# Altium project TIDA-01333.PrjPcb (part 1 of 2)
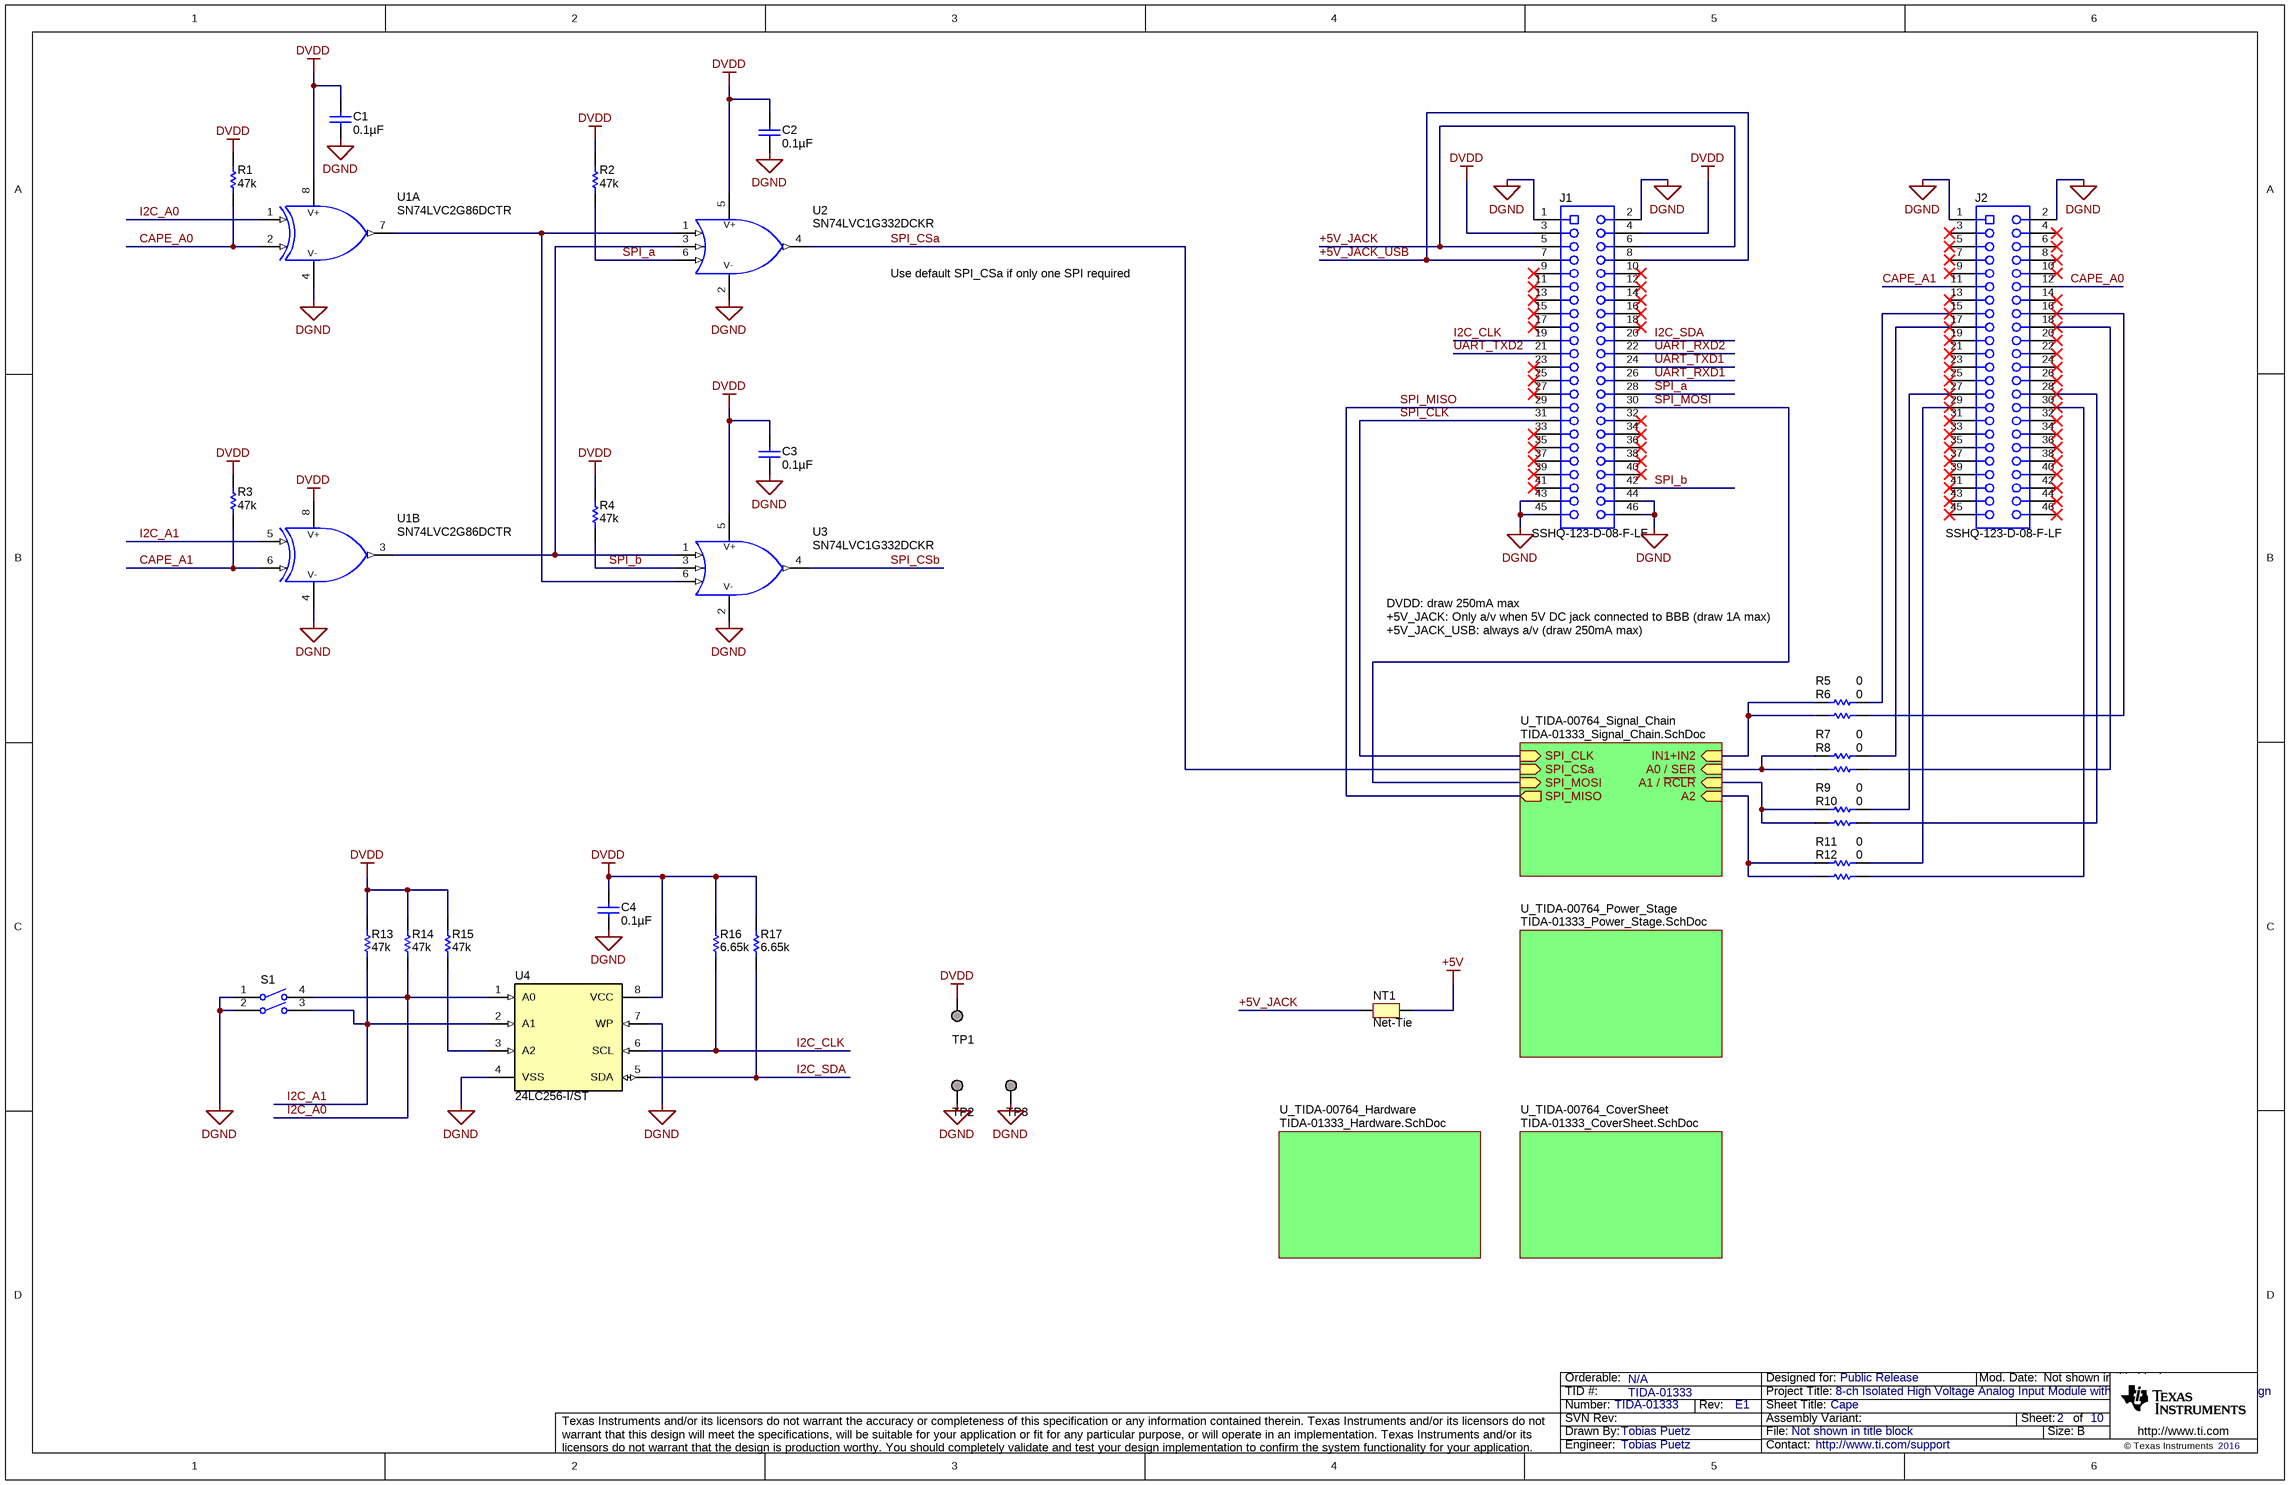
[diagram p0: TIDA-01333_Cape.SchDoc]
CopyrightYear: 2016; EVM_Orderable: N/A; PCB_Layout: Tobias Puetz; PCB_Rev: E1; PRJ_Customer: Public Release; PRJ_Engineer: Tobias Puetz; PRJ_Number: TIDA-01333; PRJ_Title: 8-ch Isolated High Voltage Analog Input Module with ISOW7841 Reference Design; SCH_Rev: E1; TechSupport: http://www.ti.com/support; TID: TIDA-01333
10 sheets, 243 parts. Net scope: hierarchical (ports join the sheet entries above them; power ports are global).
Board file: TIDA-01333.PcbDoc
Sheets:
  TIDA-01333_Cape.SchDoc
    U_TIDA-00764_Hardware = TIDA-01333_Hardware.SchDoc
    U_TIDA-00764_Signal_Chain = TIDA-01333_Signal_Chain.SchDoc
      Channel_Inputs = TIDA-01333_Channel_Inputs.SchDoc
        CMCh1 = TIDA-01333_CMCh_Input.SchDoc
        CMCh3 = TIDA-01333_CMCh_Input.SchDoc
        CMCh2 = TIDA-01333_CMCh_Input.SchDoc
        CMCh4 = TIDA-01333_CMCh_Input.SchDoc
        NoCMCh1 = TIDA-01333_Ch_Input.SchDoc
        NoCMCh2 = TIDA-01333_Ch_Input.SchDoc
        NoCMCh3 = TIDA-01333_Ch_Input.SchDoc
        NoCMCh4 = TIDA-01333_Ch_Input.SchDoc
      MUX_Stage = TIDA-01333_MUX_Stage.SchDoc
      Digital_Isolation = TIDA-01333_Digital_Isolation.SchDoc
    U_TIDA-00764_Power_Stage = TIDA-01333_Power_Stage.SchDoc
    U_TIDA-00764_CoverSheet = TIDA-01333_CoverSheet.SchDoc

## Sheet TIDA-01333_Cape.SchDoc: Cape
size 431 x 279 mm; Date: Not shown in title block; ApprovedBy: Not shown in title block; CheckedBy: Not shown in title block; Author: Not shown in title block; CompanyName: Not shown in title block; DrawnBy: Tobias Puetz; Engineer: Not shown in title block; Organization: Not shown in title block; Address1: Not shown in title block; Address2: Not shown in title block; Address3: Not shown in title block; Address4: Not shown in title block; DocumentNumber: 2; Revision: Use project parameter SCH_Rev; SheetNumber: 2; SheetTotal: 10; PageSetup: Record=PageOptions¦CenterHorizontal=True¦CenterVertical=True¦PrintScale=0.62¦XCorrection=1.00¦YCorrection=1.00¦PrintKind=0¦BorderSize=5000000¦LeftOffset=0¦BottomOffset=0¦Orientation=2¦PaperLength=1000¦PaperWidth=1000¦Scale=100¦PaperSource=15¦PrintQuality=600¦MediaType=1¦DitherType=10¦PrintScaleMode=1¦PaperKind=Letter

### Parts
C1  ValueDisplayed: 0.1µF  [0402]  (hidden comment: C1005X7R1H104K050BB)
C2  ValueDisplayed: 0.1µF  [0402]  (hidden comment: C1005X7R1H104K050BB)
C3  ValueDisplayed: 0.1µF  [0402]  (hidden comment: C1005X7R1H104K050BB)
C4  ValueDisplayed: 0.1µF  [0402]  (hidden comment: C1005X7R1H104K050BB)
J1  SSHQ-123-D-08-F-LF  [Major_BBB_SSHQ-123-D-08]
J2  SSHQ-123-D-08-F-LF  [Major_BBB_SSHQ-123-D-08]
NT1  Net-Tie  [Net-Tie_20milWide_60milLong]  (net tie, no BOM)
R1  ValueDisplayed: 47k  [0402]  (hidden comment: CRCW040247K0JNED)
R2  ValueDisplayed: 47k  [0402]  (hidden comment: CRCW040247K0JNED)
R3  ValueDisplayed: 47k  [0402]  (hidden comment: CRCW040247K0JNED)
R4  ValueDisplayed: 47k  [0402]  (hidden comment: CRCW040247K0JNED)
R5  ValueDisplayed: 0  [0603]  (hidden comment: CRCW06030000Z0EA)
R6  ValueDisplayed: 0  [0603]  (hidden comment: CRCW06030000Z0EA)
R7  ValueDisplayed: 0  [0603]  (hidden comment: CRCW06030000Z0EA)
R8  ValueDisplayed: 0  [0603]  (hidden comment: CRCW06030000Z0EA)
R9  ValueDisplayed: 0  [0603]  (hidden comment: CRCW06030000Z0EA)
R10  ValueDisplayed: 0  [0603]  (hidden comment: CRCW06030000Z0EA)
R11  ValueDisplayed: 0  [0603]  (hidden comment: CRCW06030000Z0EA)
R12  ValueDisplayed: 0  [0603]  (hidden comment: CRCW06030000Z0EA)
R13  ValueDisplayed: 47k  [0402]  (hidden comment: CRCW040247K0JNED)
R14  ValueDisplayed: 47k  [0402]  (hidden comment: CRCW040247K0JNED)
R15  ValueDisplayed: 47k  [0402]  (hidden comment: CRCW040247K0JNED)
R16  ValueDisplayed: 6.65k  [0402]  (hidden comment: CRCW04026K65FKED)
R17  ValueDisplayed: 6.65k  [0402]  (hidden comment: CRCW04026K65FKED)
S1  416131160802  [SW_416131160802]  (value not drawn)
TP1  TESTPOINT  [TESTPOINT]  (value not drawn)  (no BOM)
TP2  TESTPOINT  [TESTPOINT]  (value not drawn)  (no BOM)
TP3  TESTPOINT  [TESTPOINT]  (value not drawn)  (no BOM)
U1  SN74LVC2G86DCTR  [DCT0008A_N]  (parts A,B of 2)
U2  SN74LVC1G332DCKR  [DCK0006A_N]
U3  SN74LVC1G332DCKR  [DCK0006A_N]
U4  24LC256-I/ST  [TSSOP-8]

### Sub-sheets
U_TIDA-00764_CoverSheet = TIDA-01333_CoverSheet.SchDoc: no entries
U_TIDA-00764_Hardware = TIDA-01333_Hardware.SchDoc: no entries
U_TIDA-00764_Power_Stage = TIDA-01333_Power_Stage.SchDoc: no entries
U_TIDA-00764_Signal_Chain = TIDA-01333_Signal_Chain.SchDoc: SPI_CSa (in), SPI_CLK (in), SPI_MISO (out), SPI_MOSI (in), A2 (in), A1 / ~{RCLR} (in), A0 / SER (in), IN1+IN2 (in)

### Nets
+5V: NT1.2
DGND: C1.2 C2.2 C3.2 C4.2 J1.1 J1.2 J1.43 J1.44 J1.45 J1.46 J2.1 J2.2 S1.1 S1.2 TP2.1 TP3.1 U1.4(GND) U2.2(GND) U3.2(GND) U4.4(VSS) U4.7(WP)
DVDD: C1.1 C2.1 C3.1 C4.1 J1.3 J1.4 R1.1 R2.1 R3.1 R4.1 R13.1 R14.1 R15.1 R16.1 R17.1 TP1.1 U1.8(VCC) U2.5(VCC) U3.5(VCC) U4.8(VCC)
+5V_JACK: J1.5 J1.6 NT1.1
+5V_JACK_USB: J1.7 J1.8
A0 / SER: R7.2 R8.2 ; sheet U_TIDA-00764_Signal_Chain/A0 / SER
A1 / ~{RCLR}: R9.2 R10.2 ; sheet U_TIDA-00764_Signal_Chain/A1 / ~{RCLR}
A2: R11.2 R12.2 ; sheet U_TIDA-00764_Signal_Chain/A2
CAPE_A0: J2.12 R1.2 U1.2(1B)
CAPE_A1: J2.11 R3.2 U1.6(2B)
I2C_A0: R14.2 S1.4 U1.1(1A) U4.1(A0)
I2C_A1: R13.2 S1.3 U1.5(2A) U4.2(A1)
I2C_CLK: J1.19 R16.2 U4.6(SCL)
I2C_SDA: J1.20 R17.2 U4.5(SDA)
IN1+IN2: R5.2 R6.2 ; sheet U_TIDA-00764_Signal_Chain/IN1+IN2
SPI_a: J1.28 R2.2 U2.6(C)
SPI_b: J1.42 R4.2 U3.3(B)
SPI_CLK: J1.31 ; sheet U_TIDA-00764_Signal_Chain/SPI_CLK
SPI_CSa: U2.4(Y) ; sheet U_TIDA-00764_Signal_Chain/SPI_CSa
SPI_CSb: U3.4(Y)
SPI_MISO: J1.29 ; sheet U_TIDA-00764_Signal_Chain/SPI_MISO
SPI_MOSI: J1.30 ; sheet U_TIDA-00764_Signal_Chain/SPI_MOSI
UART_RXD1: J1.26
UART_RXD2: J1.22
UART_TXD1: J1.24
UART_TXD2: J1.21
NetJ2_15: J2.15 R5.1
NetJ2_16: J2.16 R6.1
NetJ2_17: J2.17 R7.1
NetJ2_18: J2.18 R8.1
NetJ2_27: J2.27 R9.1
NetJ2_28: J2.28 R10.1
NetJ2_29: J2.29 R11.1
NetJ2_30: J2.30 R12.1
NetR15_2: R15.2 U4.3(A2)
NetU1_3: U1.3(2Y) U2.3(B) U3.1(A)
NetU1_7: U1.7(1Y) U2.1(A) U3.6(C)

Not connected (* = marked no-connect by the designer): J1 9* 10* 11* 12* 13* 14* 15* 16* 17* 18* 23* 25* 27* 32* 33* 34* 35* 36* 37* 38* 39* 40* 41*; J2 3* 4* 5* 6* 7* 8* 9* 10* 13* 14* 19* 20* 21* 22* 23* 24* 25* 26* 31* 32* 33* 34* 35* 36* 37* 38* 39* 40* 41* 42* 43* 44* 45* 46*

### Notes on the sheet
- Use default SPI_CSa if only one SPI required
- DVDD: draw 250mA max
  +5V_JACK: Only a/v when 5V DC jack connected to BBB (draw 1A max)
  +5V_JACK_USB: always a/v (draw 250mA max)

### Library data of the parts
C1-C4 = C1005X7R1H104K050BB: CAP, CERM, 0.1 µF, 50 V, +/- 10%, X7R, 0402; Manufacturer: TDK; Polarized: N; CompType: Capacitor; Value: 0.1uF; U/M: EA; Cap_F: 0.0000001; Tolerance_%: 10; ESR_ohm: 0.039064; Value1: 0.039064 ohm; VDC_V: 50; Value2: 50V; IRMS_A: 0.814669; TaMin_C: -55; TaMax_C: 125; AEC Category: Q200; SizeArea_mm2: 0.5; SizeAreaWB_mm2: 3; SizeX_mm: 1; SizeZ_mm: 0.6
J1 J2 = SSHQ-123-D-08-F-LF: Female Connector, 2.54mm, 23x2, TH; Manufacturer: Major League Electronics; SymbolCreator: Altium; CompType: Receptacle
NT1 = Net-Tie: Single point connection between nets.; SymbolCreator: codlsc
R1-R4 R13-R15 = CRCW040247K0JNED: RES, 47 k, 5%, 0.063 W, 0402; Manufacturer: Vishay-Dale; CompType: Resistor; Value: 47k; Res_ohm: 47000; Value_Code: 47k0; Tolerance_%: 5; Power_W: 0.063; Value2: 0.063W; VDC_V: 50; TempCo: 200 ppm/C; EIA_Code: E24; U/M: EA; AEC Category: Q200; SizeArea_mm2: 0.5; SizeX_mm: 1; SizeZ_mm: 0.6
R5-R12 = CRCW06030000Z0EA: RES, 0, 5%, 0.1 W, 0603; Manufacturer: Vishay-Dale; CompType: Resistor; Value: 0; Value_Code: 0000; Tolerance_%: 5; Power_W: 0.1; Value2: 0.1W; VDC_V: 75; TempCo: 200 ppm/C; EIA_Code: E24; U/M: EA; AEC Category: Q200; SizeArea_mm2: 1.28; SizeX_mm: 1.6; SizeY_mm: 0.8; SizeZ_mm: 1
R16 R17 = CRCW04026K65FKED: RES, 6.65 k, 1%, 0.063 W, 0402; Manufacturer: Vishay-Dale; CompType: Resistor; Value: 6.65k; Res_ohm: 6650; Value_Code: 6k65; Tolerance_%: 1; Power_W: 0.063; Value2: 0.063W; VDC_V: 50; TempCo: 100 ppm/C; EIA_Code: E96; U/M: EA; AEC Category: Q200; SizeArea_mm2: 0.5; SizeZ_mm: 0.6
S1 = 416131160802: Switch, SPST, Off-On, 2 Pos, SMD; Manufacturer: Wurth Elektronik; SymbolCreator: Altium; VDC_V: 24; PositionCount: 2; CurrentRating_mA: 25
TP1-TP3 = TESTPOINT: TEST POINT.  No entry in BOM.
U1 = SN74LVC2G86DCTR: Dual 2-Input Exclusive-OR Gate, DCT0008A; Manufacturer: Texas Instruments; SymbolCreator: a0411947; CompType: IC; U/M: EA; SizeArea_mm2: 11.2; SizeAreaWB_mm2: 19; SizeX_mm: 4; SizeY_mm: 2.8; SizeZ_mm: 1.3
U2 U3 = SN74LVC1G332DCKR: Single 3-Input Positive-OR Gate, DCK0006A; Manufacturer: Texas Instruments; SymbolCreator: Altium; CompType: IC; U/M: EA; SizeArea_mm2: 4.2; SizeAreaWB_mm2: 9.3; SizeX_mm: 2.1; SizeY_mm: 2; SizeZ_mm: 1.1
U4 = 24LC256-I/ST: 256K I2C CMOS Serial EEPROM, TSSOP-8; Manufacturer: Microchip; SymbolCreator: a0411947

## Sheet TIDA-01333_Hardware.SchDoc: Hardware
size 431 x 279 mm; Date: Not shown in title block; ApprovedBy: Not shown in title block; CheckedBy: Not shown in title block; Author: Not shown in title block; CompanyName: Not shown in title block; DrawnBy: Tobias Puetz; Engineer: Not shown in title block; Organization: Not shown in title block; Address1: Not shown in title block; Address2: Not shown in title block; Address3: Not shown in title block; Address4: Not shown in title block; DocumentNumber: 3; Revision: Use project parameter SCH_Rev; SheetNumber: 3; SheetTotal: 10; PageSetup: Record=PageOptions¦CenterHorizontal=True¦CenterVertical=True¦PrintScale=1.00¦XCorrection=1.00¦YCorrection=1.00¦PrintKind=0¦BorderSize=5000000¦LeftOffset=0¦BottomOffset=0¦Orientation=2¦PaperLength=1000¦PaperWidth=1000¦Scale=100¦PaperSource=15¦PrintQuality=600¦MediaType=1¦DitherType=10¦PaperKind=Letter¦PrintScaleMode=1
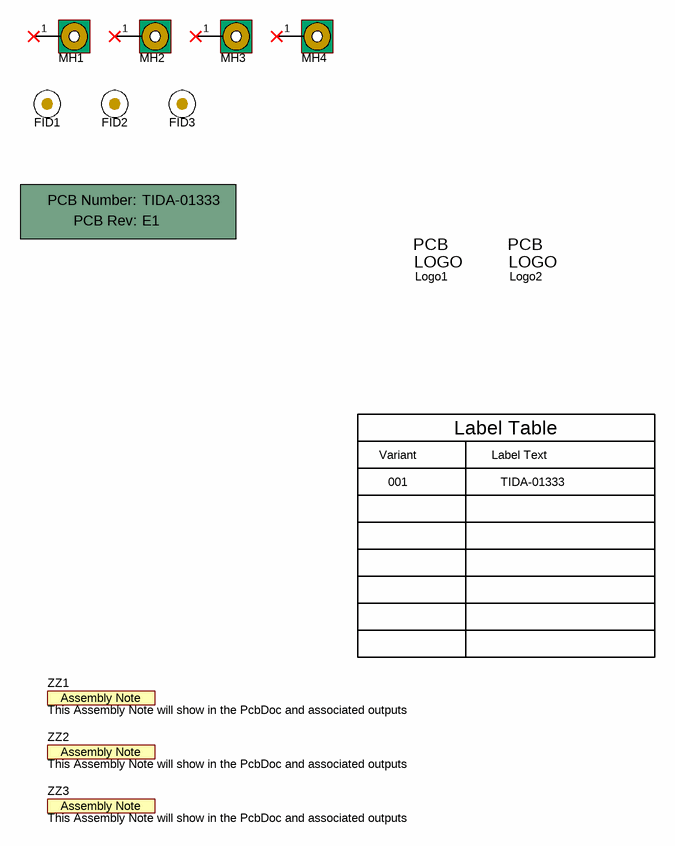
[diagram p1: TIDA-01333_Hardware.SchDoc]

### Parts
!PCB1  Printed Circuit Board  (value not drawn)  (mechanical)
FID1  Fiducial  [Fiducial10-20]  (value not drawn)
FID2  Fiducial  [Fiducial10-20]  (value not drawn)
FID3  Fiducial  [Fiducial10-20]  (value not drawn)
Logo1  Pb-Free Symbol  [Pb-Free_Overlay_Small]  (value not drawn)  (no BOM)
Logo2  FCC disclaimer  [FCC_disclaimer_stacked]  (value not drawn)  (no BOM)
MH1  MTG_Pads  [MTGP_4-40_PanHead]  (value not drawn)  (no BOM)
MH2  MTG_Pads  [MTGP_4-40_PanHead]  (value not drawn)  (no BOM)
MH3  MTG_Pads  [MTGP_4-40_PanHead]  (value not drawn)  (no BOM)
MH4  MTG_Pads  [MTGP_4-40_PanHead]  (value not drawn)  (no BOM)
ZZ1  This Assembly Note will show in the PcbDoc and associated outputs  [AssemblyNote]  (no BOM)
ZZ2  This Assembly Note will show in the PcbDoc and associated outputs  [AssemblyNote]  (no BOM)
ZZ3  This Assembly Note will show in the PcbDoc and associated outputs  [AssemblyNote]  (no BOM)

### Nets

Not connected (* = marked no-connect by the designer): MH1 1*; MH2 1*; MH3 1*; MH4 1*

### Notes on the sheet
- Variant
- Label Table
- Label Text
- 001
- TIDA-01333

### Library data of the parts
!PCB1 = PCB: Manufacturer: Any; PartNumber: TIDA-01333; SymbolCreator: a0412235
FID1-FID3 = Fiducial: Fiducial mark.  There is nothing to buy or mount.; SymbolCreator: codlsc
Logo1 = Pb-Free: SymbolCreator: a0412235
Logo2 = FCC_disclaimer: SymbolCreator: a0412235
MH1-MH4 = Mounting Hole (Imperial) with Pads: PCB Mounting Hole; Manufacturer: Any; SymbolCreator: a0412235
ZZ1-ZZ3 = AssemblyNote: SymbolCreator: codlsc

## Sheet TIDA-01333_Signal_Chain.SchDoc: Signal Chain
size 431 x 279 mm; Date: Not shown in title block; ApprovedBy: Not shown in title block; CheckedBy: Not shown in title block; Author: Not shown in title block; CompanyName: Not shown in title block; DrawnBy: Tobias Puetz; Engineer: Not shown in title block; Organization: Not shown in title block; Address1: Not shown in title block; Address2: Not shown in title block; Address3: Not shown in title block; Address4: Not shown in title block; DocumentNumber: 5; Revision: Use project parameter SCH_Rev; SheetNumber: 5; SheetTotal: 10; PageSetup: Record=PageOptions¦CenterHorizontal=True¦CenterVertical=True¦PrintScale=1.00¦XCorrection=1.00¦YCorrection=1.00¦PrintKind=0¦BorderSize=5000000¦LeftOffset=0¦BottomOffset=0¦Orientation=2¦PaperLength=1000¦PaperWidth=1000¦Scale=100¦PaperSource=15¦PrintQuality=600¦MediaType=1¦DitherType=10¦PaperKind=Letter¦PrintScaleMode=1
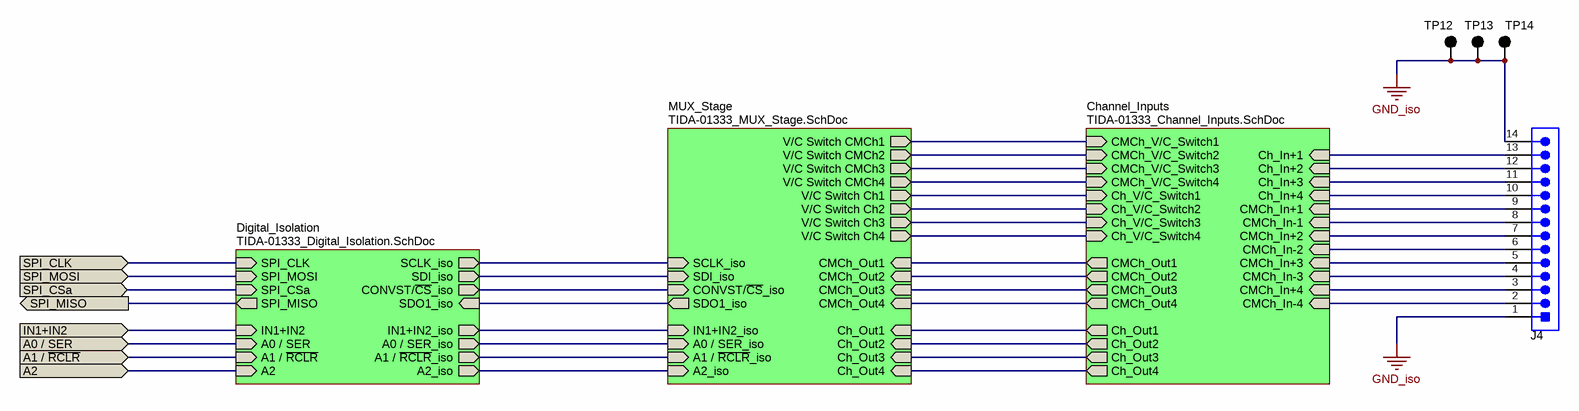
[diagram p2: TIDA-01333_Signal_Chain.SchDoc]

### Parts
J4  1844333  [Phoenix_1844333]  (value not drawn)
TP12  5001  [Keystone5001]  (value not drawn)
TP13  5001  [Keystone5001]  (value not drawn)
TP14  5001  [Keystone5001]  (value not drawn)

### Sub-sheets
Channel_Inputs = TIDA-01333_Channel_Inputs.SchDoc: Ch_Out1 (out), Ch_Out2 (out), Ch_Out4 (out), Ch_Out3 (out), CMCh_Out1 (out), CMCh_V/C_Switch1 (in), CMCh_V/C_Switch2 (in), CMCh_V/C_Switch3 (in), CMCh_V/C_Switch4 (in), Ch_V/C_Switch1 (in), Ch_V/C_Switch2 (in), Ch_V/C_Switch3 (in), Ch_V/C_Switch4 (in), CMCh_Out2 (out), CMCh_Out3 (out), CMCh_Out4 (out), CMCh_In+1 (in), CMCh_In+2 (in), CMCh_In+3 (in), CMCh_In+4 (in), CMCh_In-1 (in), CMCh_In-2 (in), CMCh_In-3 (in), CMCh_In-4 (in), Ch_In+1 (in), Ch_In+2 (in), Ch_In+3 (in), Ch_In+4 (in)
Digital_Isolation = TIDA-01333_Digital_Isolation.SchDoc: SPI_CLK (in), SPI_MOSI (in), SPI_MISO (out), A2 (in), A1 / ~{RCLR} (in), A0 / SER (in), IN1+IN2 (in), SPI_CSa (in), SCLK_iso (out), SDI_iso (out), SDO1_iso (in), CONVST/~{CS}_iso (out), A2_iso (out), A1 / ~{RCLR}_iso (out), A0 / SER_iso (out), IN1+IN2_iso (out)
MUX_Stage = TIDA-01333_MUX_Stage.SchDoc: V/C Switch CMCh1 (out), V/C Switch CMCh2 (out), V/C Switch CMCh3 (out), V/C Switch CMCh4 (out), V/C Switch Ch1 (out), V/C Switch Ch2 (out), V/C Switch Ch3 (out), V/C Switch Ch4 (out), CMCh_Out1 (in), CMCh_Out2 (in), CMCh_Out3 (in), CMCh_Out4 (in), Ch_Out1 (in), Ch_Out2 (in), Ch_Out3 (in), Ch_Out4 (in), SCLK_iso (in), SDI_iso (in), SDO1_iso (out), A2_iso (in), A0 / SER_iso (in), IN1+IN2_iso (in), CONVST/~{CS}_iso (in), A1 / ~{RCLR}_iso (in)

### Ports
A0 / SER (in), A1 / ~{RCLR} (in), A2 (in), IN1+IN2 (in), SPI_CLK (in), SPI_CSa (in), SPI_MISO (out), SPI_MOSI (in)

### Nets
GND_iso: J4.1 J4.14 TP12.1 TP13.1 TP14.1
A0 / SER: port A0 / SER, sheet Digital_Isolation/A0 / SER
A0 / SER_iso: sheet MUX_Stage/A0 / SER_iso, sheet Digital_Isolation/A0 / SER_iso
A1 / ~{RCLR}: port A1 / ~{RCLR}, sheet Digital_Isolation/A1 / ~{RCLR}
A1 / ~{RCLR}_iso: sheet MUX_Stage/A1 / ~{RCLR}_iso, sheet Digital_Isolation/A1 / ~{RCLR}_iso
A2: port A2, sheet Digital_Isolation/A2
A2_iso: sheet MUX_Stage/A2_iso, sheet Digital_Isolation/A2_iso
Ch_In+: J4.10 ; sheet Channel_Inputs/Ch_Out4, sheet Channel_Inputs/Ch_In+4, sheet MUX_Stage/Ch_Out4
Ch_In+: J4.11 ; sheet Channel_Inputs/Ch_Out3, sheet Channel_Inputs/Ch_In+3, sheet MUX_Stage/Ch_Out3  [a separate net that carries the same name]
Ch_In+: J4.12 ; sheet Channel_Inputs/Ch_Out2, sheet Channel_Inputs/Ch_In+2, sheet MUX_Stage/Ch_Out2  [a separate net that carries the same name]
Ch_In+: J4.13 ; sheet Channel_Inputs/Ch_Out1, sheet Channel_Inputs/Ch_In+1, sheet MUX_Stage/Ch_Out1  [a separate net that carries the same name]
Ch_V/C_Switch: sheet Channel_Inputs/Ch_V/C_Switch1, sheet MUX_Stage/V/C Switch Ch1
Ch_V/C_Switch: sheet Channel_Inputs/Ch_V/C_Switch2, sheet MUX_Stage/V/C Switch Ch2  [a separate net that carries the same name]
Ch_V/C_Switch: sheet Channel_Inputs/Ch_V/C_Switch3, sheet MUX_Stage/V/C Switch Ch3  [a separate net that carries the same name]
Ch_V/C_Switch: sheet Channel_Inputs/Ch_V/C_Switch4, sheet MUX_Stage/V/C Switch Ch4  [a separate net that carries the same name]
CMCh_In+: J4.5 ; sheet Channel_Inputs/CMCh_In+3
CMCh_In+: J4.3 ; sheet Channel_Inputs/CMCh_In+4  [a separate net that carries the same name]
CMCh_In+: J4.7 ; sheet Channel_Inputs/CMCh_In+2  [a separate net that carries the same name]
CMCh_In+: J4.9 ; sheet Channel_Inputs/CMCh_In+1  [a separate net that carries the same name]
CMCh_In-: J4.4 ; sheet Channel_Inputs/CMCh_In-3
CMCh_In-: J4.2 ; sheet Channel_Inputs/CMCh_In-4  [a separate net that carries the same name]
CMCh_In-: J4.6 ; sheet Channel_Inputs/CMCh_In-2  [a separate net that carries the same name]
CMCh_In-: J4.8 ; sheet Channel_Inputs/CMCh_In-1  [a separate net that carries the same name]
CMCh_Out: sheet Channel_Inputs/CMCh_Out1, sheet MUX_Stage/CMCh_Out1
CMCh_Out: sheet Channel_Inputs/CMCh_Out3, sheet MUX_Stage/CMCh_Out3  [a separate net that carries the same name]
CMCh_Out: sheet Channel_Inputs/CMCh_Out2, sheet MUX_Stage/CMCh_Out2  [a separate net that carries the same name]
CMCh_Out: sheet Channel_Inputs/CMCh_Out4, sheet MUX_Stage/CMCh_Out4  [a separate net that carries the same name]
CMCh_V/C_Switch: sheet Channel_Inputs/CMCh_V/C_Switch1, sheet MUX_Stage/V/C Switch CMCh1
CMCh_V/C_Switch: sheet Channel_Inputs/CMCh_V/C_Switch3, sheet MUX_Stage/V/C Switch CMCh3  [a separate net that carries the same name]
CMCh_V/C_Switch: sheet Channel_Inputs/CMCh_V/C_Switch2, sheet MUX_Stage/V/C Switch CMCh2  [a separate net that carries the same name]
CMCh_V/C_Switch: sheet Channel_Inputs/CMCh_V/C_Switch4, sheet MUX_Stage/V/C Switch CMCh4  [a separate net that carries the same name]
CONVST/~{CS}_iso: sheet MUX_Stage/CONVST/~{CS}_iso, sheet Digital_Isolation/CONVST/~{CS}_iso
IN1+IN2: port IN1+IN2, sheet Digital_Isolation/IN1+IN2
IN1+IN2_iso: sheet MUX_Stage/IN1+IN2_iso, sheet Digital_Isolation/IN1+IN2_iso
SCLK_iso: sheet MUX_Stage/SCLK_iso, sheet Digital_Isolation/SCLK_iso
SDI_iso: sheet MUX_Stage/SDI_iso, sheet Digital_Isolation/SDI_iso
SDO1_iso: sheet MUX_Stage/SDO1_iso, sheet Digital_Isolation/SDO1_iso
SPI_CLK: port SPI_CLK, sheet Digital_Isolation/SPI_CLK
SPI_CSa: port SPI_CSa, sheet Digital_Isolation/SPI_CSa
SPI_MISO: port SPI_MISO, sheet Digital_Isolation/SPI_MISO
SPI_MOSI: port SPI_MOSI, sheet Digital_Isolation/SPI_MOSI

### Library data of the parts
J4 = 1844333: Header (Shrouded), 3.5mm, 14x1, Tin, R/A, TH; Manufacturer: Phoenix Contact; SymbolCreator: a0411947; Pitch_mm: 3.5; Gender: Male; Shrouded: Y; Row_Count: 1; Current_A: 8; Voltage_V: 160
TP12-TP14 = 5001: Test Point, Miniature, Black, TH; Manufacturer: Keystone; CompType: Test Point Loop; ContactFinish: Silver

## Sheet TIDA-01333_Channel_Inputs.SchDoc: Channel Inputs
size 431 x 279 mm; Date: Not shown in title block; ApprovedBy: Not shown in title block; CheckedBy: Not shown in title block; Author: Not shown in title block; CompanyName: Not shown in title block; DrawnBy: Tobias Puetz; Engineer: Not shown in title block; Organization: Not shown in title block; Address1: Not shown in title block; Address2: Not shown in title block; Address3: Not shown in title block; Address4: Not shown in title block; DocumentNumber: 6; Revision: Use project parameter SCH_Rev; SheetNumber: 6; SheetTotal: 10; PageSetup: Record=PageOptions¦CenterHorizontal=True¦CenterVertical=True¦PrintScale=1.00¦XCorrection=1.00¦YCorrection=1.00¦PrintKind=0¦BorderSize=5000000¦LeftOffset=0¦BottomOffset=0¦Orientation=2¦PaperLength=1000¦PaperWidth=1000¦Scale=100¦PaperSource=15¦PrintQuality=600¦MediaType=1¦DitherType=10¦PaperKind=Letter¦PrintScaleMode=1
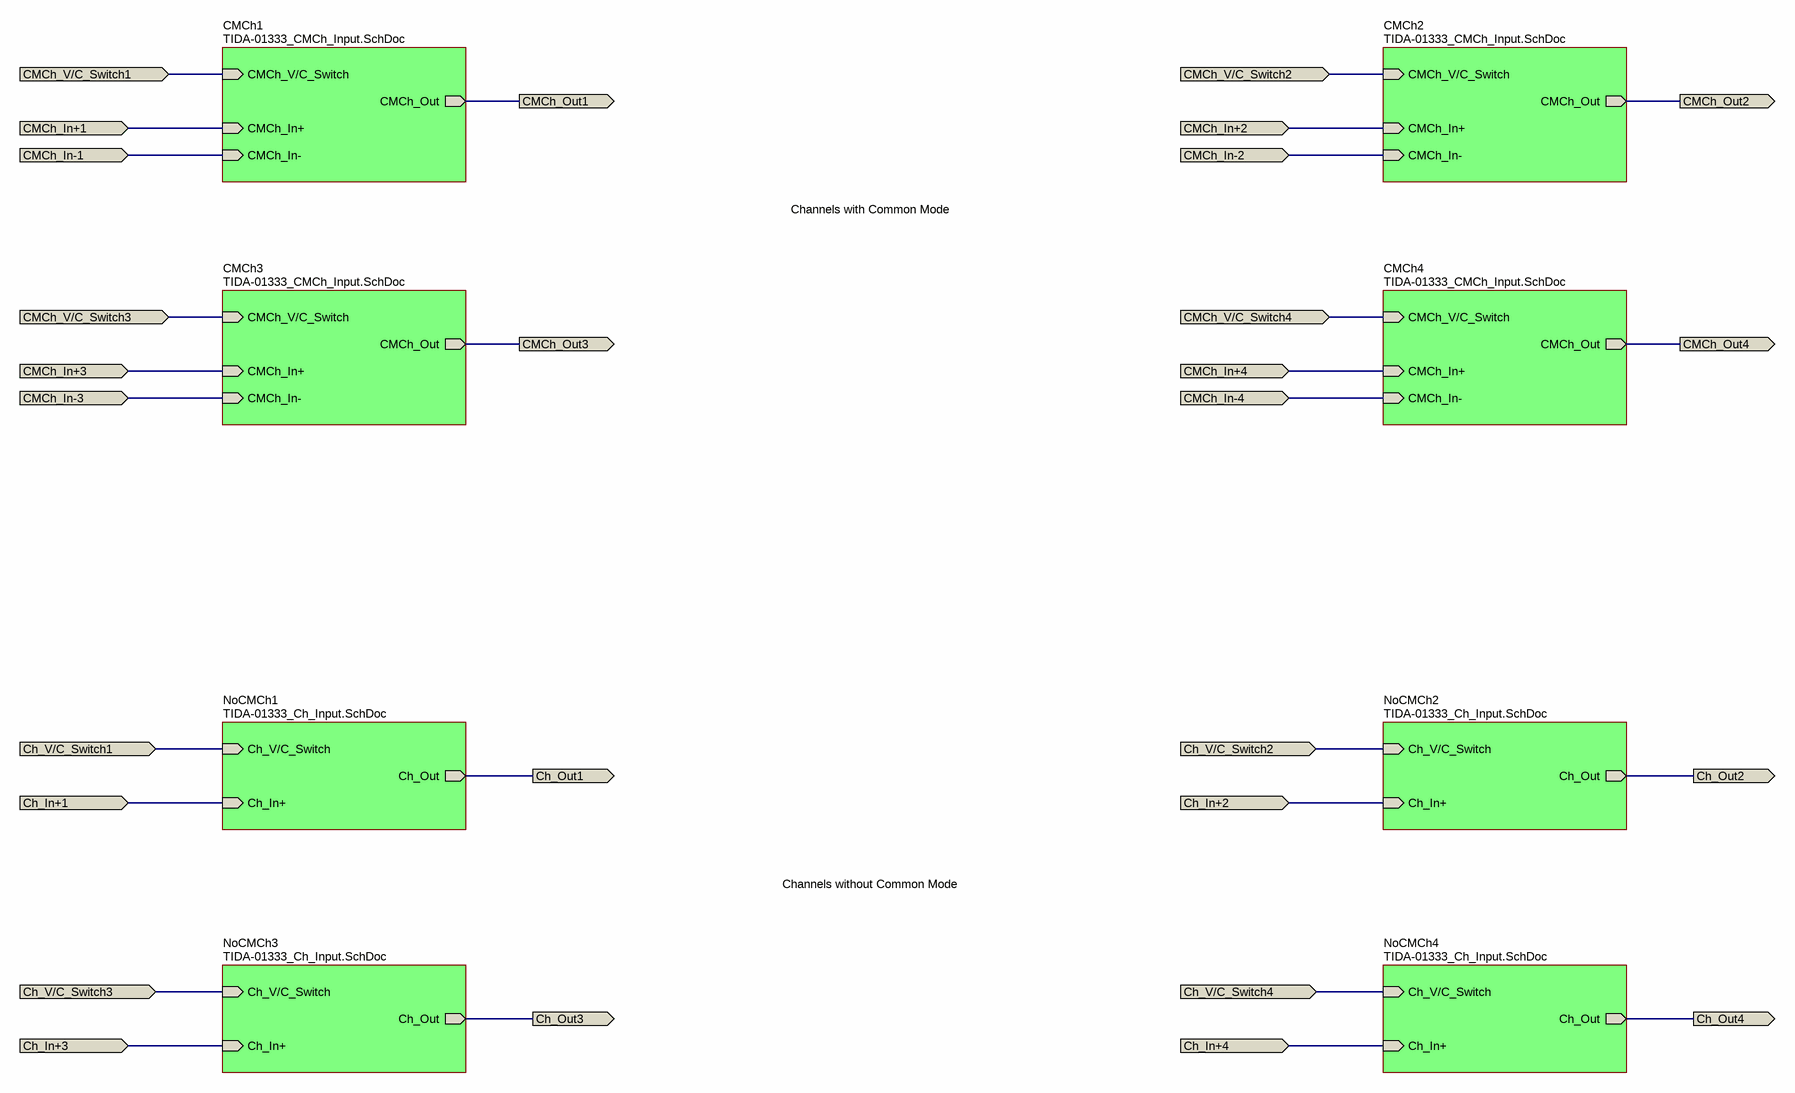
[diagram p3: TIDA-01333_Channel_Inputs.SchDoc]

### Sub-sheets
CMCh1 = TIDA-01333_CMCh_Input.SchDoc: CMCh_V/C_Switch (in), CMCh_Out (out), CMCh_In+ (in), CMCh_In- (in)
CMCh2 = TIDA-01333_CMCh_Input.SchDoc: CMCh_V/C_Switch (in), CMCh_Out (out), CMCh_In+ (in), CMCh_In- (in)
CMCh3 = TIDA-01333_CMCh_Input.SchDoc: CMCh_V/C_Switch (in), CMCh_Out (out), CMCh_In+ (in), CMCh_In- (in)
CMCh4 = TIDA-01333_CMCh_Input.SchDoc: CMCh_V/C_Switch (in), CMCh_Out (out), CMCh_In+ (in), CMCh_In- (in)
NoCMCh1 = TIDA-01333_Ch_Input.SchDoc: Ch_V/C_Switch (in), Ch_Out (out), Ch_In+ (in)
NoCMCh2 = TIDA-01333_Ch_Input.SchDoc: Ch_V/C_Switch (in), Ch_Out (out), Ch_In+ (in)
NoCMCh3 = TIDA-01333_Ch_Input.SchDoc: Ch_V/C_Switch (in), Ch_Out (out), Ch_In+ (in)
NoCMCh4 = TIDA-01333_Ch_Input.SchDoc: Ch_V/C_Switch (in), Ch_Out (out), Ch_In+ (in)

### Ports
Ch_In+1 (in), Ch_In+2 (in), Ch_In+3 (in), Ch_In+4 (in), Ch_Out1 (out), Ch_Out2 (out), Ch_Out3 (out), Ch_Out4 (out), Ch_V/C_Switch1 (in), Ch_V/C_Switch2 (in), Ch_V/C_Switch3 (in), Ch_V/C_Switch4 (in), CMCh_In+1 (in), CMCh_In+2 (in), CMCh_In+3 (in), CMCh_In+4 (in), CMCh_In-1 (in), CMCh_In-2 (in), CMCh_In-3 (in), CMCh_In-4 (in), CMCh_Out1 (out), CMCh_Out2 (out), CMCh_Out3 (out), CMCh_Out4 (out), CMCh_V/C_Switch1 (in), CMCh_V/C_Switch2 (in), CMCh_V/C_Switch3 (in), CMCh_V/C_Switch4 (in)

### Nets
Ch_In+: port Ch_Out4, port Ch_In+4, sheet NoCMCh4/Ch_Out, sheet NoCMCh4/Ch_In+
Ch_In+: port Ch_Out3, port Ch_In+3, sheet NoCMCh3/Ch_Out, sheet NoCMCh3/Ch_In+  [a separate net that carries the same name]
Ch_In+: port Ch_Out2, port Ch_In+2, sheet NoCMCh2/Ch_Out, sheet NoCMCh2/Ch_In+  [a separate net that carries the same name]
Ch_In+: port Ch_Out1, port Ch_In+1, sheet NoCMCh1/Ch_Out, sheet NoCMCh1/Ch_In+  [a separate net that carries the same name]
Ch_V/C_Switch: port Ch_V/C_Switch1, sheet NoCMCh1/Ch_V/C_Switch
Ch_V/C_Switch: port Ch_V/C_Switch2, sheet NoCMCh2/Ch_V/C_Switch  [a separate net that carries the same name]
Ch_V/C_Switch: port Ch_V/C_Switch3, sheet NoCMCh3/Ch_V/C_Switch  [a separate net that carries the same name]
Ch_V/C_Switch: port Ch_V/C_Switch4, sheet NoCMCh4/Ch_V/C_Switch  [a separate net that carries the same name]
CMCh_In+: port CMCh_In+3, sheet CMCh3/CMCh_In+
CMCh_In+: port CMCh_In+4, sheet CMCh4/CMCh_In+  [a separate net that carries the same name]
CMCh_In+: port CMCh_In+2, sheet CMCh2/CMCh_In+  [a separate net that carries the same name]
CMCh_In+: port CMCh_In+1, sheet CMCh1/CMCh_In+  [a separate net that carries the same name]
CMCh_In-: port CMCh_In-3, sheet CMCh3/CMCh_In-
CMCh_In-: port CMCh_In-4, sheet CMCh4/CMCh_In-  [a separate net that carries the same name]
CMCh_In-: port CMCh_In-2, sheet CMCh2/CMCh_In-  [a separate net that carries the same name]
CMCh_In-: port CMCh_In-1, sheet CMCh1/CMCh_In-  [a separate net that carries the same name]
CMCh_Out: port CMCh_Out1, sheet CMCh1/CMCh_Out
CMCh_Out: port CMCh_Out3, sheet CMCh3/CMCh_Out  [a separate net that carries the same name]
CMCh_Out: port CMCh_Out2, sheet CMCh2/CMCh_Out  [a separate net that carries the same name]
CMCh_Out: port CMCh_Out4, sheet CMCh4/CMCh_Out  [a separate net that carries the same name]
CMCh_V/C_Switch: port CMCh_V/C_Switch1, sheet CMCh1/CMCh_V/C_Switch
CMCh_V/C_Switch: port CMCh_V/C_Switch3, sheet CMCh3/CMCh_V/C_Switch  [a separate net that carries the same name]
CMCh_V/C_Switch: port CMCh_V/C_Switch2, sheet CMCh2/CMCh_V/C_Switch  [a separate net that carries the same name]
CMCh_V/C_Switch: port CMCh_V/C_Switch4, sheet CMCh4/CMCh_V/C_Switch  [a separate net that carries the same name]

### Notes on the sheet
- Channels with Common Mode
- Channels without Common Mode

## Sheet TIDA-01333_CMCh_Input.SchDoc: CM Ch Input
size 431 x 279 mm; Date: Not shown in title block; ApprovedBy: Not shown in title block; CheckedBy: Not shown in title block; Author: Not shown in title block; CompanyName: Not shown in title block; DrawnBy: Tobias Puetz; Engineer: Not shown in title block; Organization: Not shown in title block; Address1: Not shown in title block; Address2: Not shown in title block; Address3: Not shown in title block; Address4: Not shown in title block; DocumentNumber: 8; Revision: Use project parameter SCH_Rev; SheetNumber: 8; SheetTotal: 10; PageSetup: Record=PageOptions¦CenterHorizontal=True¦CenterVertical=True¦PrintScale=1.00¦XCorrection=1.00¦YCorrection=1.00¦PrintKind=0¦BorderSize=5000000¦LeftOffset=0¦BottomOffset=0¦Orientation=2¦PaperLength=1000¦PaperWidth=1000¦Scale=100¦PaperSource=15¦PrintQuality=600¦MediaType=1¦DitherType=10¦PaperKind=Letter¦PrintScaleMode=1
Used 4 times, as channels U_TIDA-00764_Signal_Chain/Channel_Inputs/CMCh1, U_TIDA-00764_Signal_Chain/Channel_Inputs/CMCh3, U_TIDA-00764_Signal_Chain/Channel_Inputs/CMCh2, U_TIDA-00764_Signal_Chain/Channel_Inputs/CMCh4. Parts and nets are listed once, with the designators drawn on the sheet.
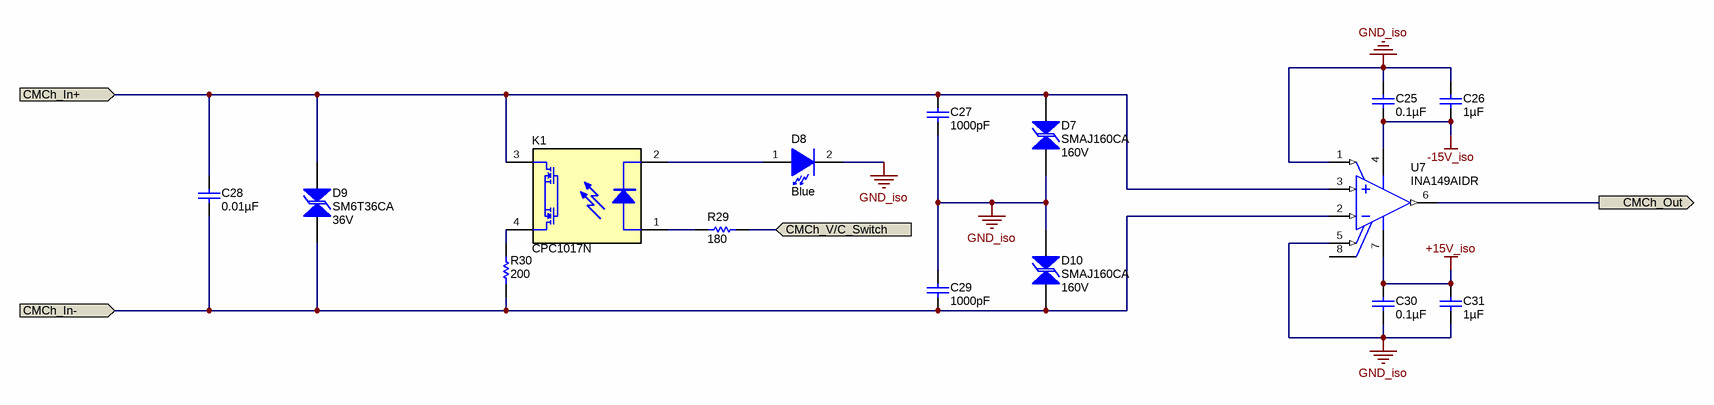
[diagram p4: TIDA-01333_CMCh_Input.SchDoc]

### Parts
C25  ValueDisplayed: 0.1µF  [0603]  (hidden comment: GRM188R71H104KA93D)
C26  ValueDisplayed: 1µF  [0603]  (hidden comment: C1608X7R1C105K080AC)
C27  ValueDisplayed: 1000pF  [0805_HV]  (hidden comment: C0805C102JBRACTU)
C28  ValueDisplayed: 0.01µF  [0603]  (hidden comment: 06031C103KAT2A)
C29  ValueDisplayed: 1000pF  [0805_HV]  (hidden comment: C0805C102JBRACTU)
C30  ValueDisplayed: 0.1µF  [0603]  (hidden comment: GRM188R71H104KA93D)
C31  ValueDisplayed: 1µF  [0603]  (hidden comment: C1608X7R1C105K080AC)
D7  SMAJ160CA  value 160V  [SMA]
D8  value Blue  [LB Q39G_BLUE]  (hidden comment: LB Q39G-L2N2-35-1)
D9  SM6T36CA  value 36V  [SMB-Bi]
D10  SMAJ160CA  value 160V  [SMA]
K1  CPC1017N  [RELAY_CPC1017N]
R29  ValueDisplayed: 180  [0603]  (hidden comment: CRCW0603180RJNEA)
R30  ValueDisplayed: 200  [0805_HV]  (hidden comment: RG2012P-201-B-T5)
U7  INA149AIDR  [D0008A_N]

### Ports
CMCh_In+ (in), CMCh_In- (in), CMCh_Out (out), CMCh_V/C_Switch (in)

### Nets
+15V_iso: C30.1 C31.1 U7.7(V+)
-15V_iso: C25.2 C26.2 U7.4(V-)
GND_iso: C25.1 C26.1 C27.2 C29.1 C30.2 C31.2 D7.2 D8.2(K) D10.2 U7.1(REFB) U7.5(REFA)
CMCh_In+: C27.1 C28.1 D7.1 D9.2 K1.3(LOAD) U7.3(IN+) ; port CMCh_In+
CMCh_In-: C28.2 C29.2 D9.1 D10.1 R30.1 U7.2(IN-) ; port CMCh_In-
CMCh_Out: U7.6(VOUT) ; port CMCh_Out
CMCh_V/C_Switch: R29.2 ; port CMCh_V/C_Switch
NetD8_1: D8.1(A) K1.2(CONTROL)
NetK1_1: K1.1(CONTROL+) R29.1
NetK1_4: K1.4(LOAD) R30.2

Not connected (* = marked no-connect by the designer): U7 8(NC)

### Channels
U_TIDA-00764_Signal_Chain/Channel_Inputs/CMCh1: designators end in _CMCh1; ports CMCh_In+=CMCh_In+ CMCh_In-=CMCh_In- CMCh_Out=CMCh_Out CMCh_V/C_Switch=CMCh_V/C_Switch
U_TIDA-00764_Signal_Chain/Channel_Inputs/CMCh3: designators end in _CMCh3; ports CMCh_In+=CMCh_In+ CMCh_In-=CMCh_In- CMCh_Out=CMCh_Out CMCh_V/C_Switch=CMCh_V/C_Switch
U_TIDA-00764_Signal_Chain/Channel_Inputs/CMCh2: designators end in _CMCh2; ports CMCh_In+=CMCh_In+ CMCh_In-=CMCh_In- CMCh_Out=CMCh_Out CMCh_V/C_Switch=CMCh_V/C_Switch
U_TIDA-00764_Signal_Chain/Channel_Inputs/CMCh4: designators end in _CMCh4; ports CMCh_In+=CMCh_In+ CMCh_In-=CMCh_In- CMCh_Out=CMCh_Out CMCh_V/C_Switch=CMCh_V/C_Switch

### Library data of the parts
C25 C30 = GRM188R71H104KA93D: CAP, CERM, 0.1 µF, 50 V, +/- 10%, X7R, 0603; Manufacturer: MuRata; Polarized: N; CompType: Capacitor; Value: 0.1uF; U/M: EA; Cap_F: 0.0000001; Tolerance_%: 10; Value1: Unknown; VDC_V: 50; Value2: 50V; TaMin_C: -55; TaMax_C: 125; SizeArea_mm2: 1.28; SizeAreaWB_mm2: 4.68; SizeX_mm: 1.6; SizeY_mm: 0.8; SizeZ_mm: 1; AEC Category: Q200
C26 C31 = C1608X7R1C105K080AC: CAP, CERM, 1 µF, 16 V, +/- 10%, X7R, 0603; Manufacturer: TDK; Polarized: N; CompType: Capacitor; Value: 1uF; U/M: EA; Cap_F: 0.000001; Tolerance_%: 10; ESR_ohm: 0.0057; Value1: 0.0057 ohm; VDC_V: 16; Value2: 16V; TaMin_C: -55; TaMax_C: 125; AEC Category: Q200; SizeArea_mm2: 1.28; SizeAreaWB_mm2: 4.68; SizeX_mm: 1.6; SizeY_mm: 0.8; SizeZ_mm: 1
C27 C29 = C0805C102JBRACTU: CAP, CERM, 1000 pF, 630 V, +/- 5%, X7R, 0805; Manufacturer: Kemet; Polarized: N; CompType: Capacitor; Value: 1000pF; U/M: EA; Cap_F: 0.000000001; Tolerance_%: 5; Value1: Unknown; VDC_V: 630; Value2: 630V; TaMin_C: -55; TaMax_C: 125; Cap_Case: 0805; AEC Category: Q200; SizeArea_mm2: 2.5; SizeAreaWB_mm2: 6.75; SizeX_mm: 2; SizeY_mm: 1.25; SizeZ_mm: 1.45
C28 = 06031C103KAT2A: CAP, CERM, 0.01 µF, 100 V, +/- 10%, X7R, 0603; Manufacturer: AVX; Polarized: N; CompType: Capacitor; Value: 0.01uF; U/M: EA; Cap_F: 0.00000001; Tolerance_%: 10; ESR_ohm: 0.098; Value1: 0.098 ohm; VDC_V: 100; Value2: 100V; TaMin_C: -55; TaMax_C: 125; SizeArea_mm2: 1.28; SizeAreaWB_mm2: 4.68; SizeX_mm: 1.6; SizeY_mm: 0.8; SizeZ_mm: 1; AEC Category: Q200
D7 D10 = SMAJ160CA: Diode, TVS, Bi, 160 V, 400 W, SMA; Manufacturer: Littelfuse; U/M: EA; Power_W: 400; Vr_V: 160; Value1: 400W; RJA_CperW: 120; AEC Category: Q101; SizeAreaWB_mm2: 37.3428; SizeArea_mm2: 16.3228; SizeX_mm: 5.59; SizeY_mm: 2.92; SizeZ_mm: 2.87
D8 = LB Q39G-L2N2-35-1: LED, Blue, SMD; Manufacturer: OSRAM; Vf_V: 2.85; Value2: 2.85V; Io_A: 0.15; Tjmax_C: 95; Value1: W; U/M: EA
D9 = SM6T36CA: Diode, TVS, Bi, 36 V, 600 W, SMB; Manufacturer: STMicroelectronics; U/M: EA; Power_W: 600; Vr_V: 36; Value1: 600W; RJA_CperW: 100; AEC Category: Q101; AEC Qualified: N
K1 = CPC1017N: Relay, SPST-NO (1 Form A), 0.1 A, 1.2 VDC, SMD; Manufacturer: IXYS; SymbolCreator: Altium; Coil Voltage: 1.2 VDC; Contact Rating: 0.1 A; Time Operate (s): 0.01
R29 = CRCW0603180RJNEA: RES, 180, 5%, 0.1 W, 0603; Manufacturer: Vishay-Dale; CompType: Resistor; Value: 180; Value_Code: 180R; Tolerance_%: 5; Power_W: 0.1; Value2: 0.1W; VDC_V: 75; TempCo: 200 ppm/C; SizeArea_mm2: 1.28; SizeX_mm: 1.6; SizeY_mm: 0.8; SizeZ_mm: 1; EIA_Code: E24; U/M: EA; AEC Category: Q200
R30 = RG2012P-201-B-T5: RES, 200, 0.1%, 0.125 W, 0805; Manufacturer: Susumu Co Ltd; CompType: Resistor; Value: 200; Value_Code: 200R; Tolerance_%: 0.1; Power_W: 0.125; Value2: 0.125W; VDC_V: 100; TempCo: 25 ppm/C; EIA_Code: E192; U/M: EA; AEC Category: Q200; SizeArea_mm2: 2.5; SizeX_mm: 2; SizeY_mm: 1.25; SizeZ_mm: 1.45
U7 = INA149AIDR: High Common-Mode Voltage Difference Amplifier, D0008A; Manufacturer: Texas Instruments; SymbolCreator: Altium; CompType: IC; U/M: EA; SizeArea_mm2: 30.38; SizeAreaWB_mm2: 56.58; SizeX_mm: 4.9; SizeY_mm: 6.2; SizeZ_mm: 1.75

## Sheet TIDA-01333_Ch_Input.SchDoc: NoCM Ch Input
size 431 x 279 mm; Date: Not shown in title block; ApprovedBy: Not shown in title block; CheckedBy: Not shown in title block; Author: Not shown in title block; CompanyName: Not shown in title block; DrawnBy: Tobias Puetz; Engineer: Not shown in title block; Organization: Not shown in title block; Address1: Not shown in title block; Address2: Not shown in title block; Address3: Not shown in title block; Address4: Not shown in title block; DocumentNumber: 7; Revision: Use project parameter SCH_Rev; SheetNumber: 7; SheetTotal: 10; PageSetup: Record=PageOptions¦CenterHorizontal=True¦CenterVertical=True¦PrintScale=1.00¦XCorrection=1.00¦YCorrection=1.00¦PrintKind=0¦BorderSize=5000000¦LeftOffset=0¦BottomOffset=0¦Orientation=2¦PaperLength=1000¦PaperWidth=1000¦Scale=100¦PaperSource=15¦PrintQuality=600¦MediaType=1¦DitherType=10¦PaperKind=Letter¦PrintScaleMode=1
Used 4 times, as channels U_TIDA-00764_Signal_Chain/Channel_Inputs/NoCMCh1, U_TIDA-00764_Signal_Chain/Channel_Inputs/NoCMCh2, U_TIDA-00764_Signal_Chain/Channel_Inputs/NoCMCh3, U_TIDA-00764_Signal_Chain/Channel_Inputs/NoCMCh4. Parts and nets are listed once, with the designators drawn on the sheet.
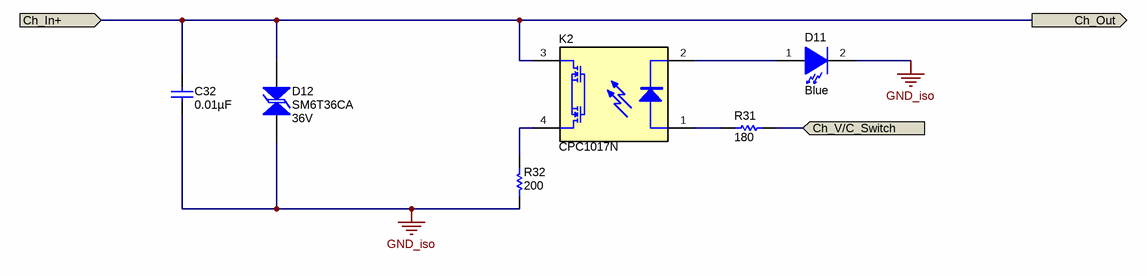
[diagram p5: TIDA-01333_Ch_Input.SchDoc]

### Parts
C32  ValueDisplayed: 0.01µF  [0603]  (hidden comment: 06031C103KAT2A)
D11  value Blue  [LB Q39G_BLUE]  (hidden comment: LB Q39G-L2N2-35-1)
D12  SM6T36CA  value 36V  [SMB-Bi]
K2  CPC1017N  [RELAY_CPC1017N]
R31  ValueDisplayed: 180  [0603]  (hidden comment: CRCW0603180RJNEA)
R32  ValueDisplayed: 200  [0805_HV]  (hidden comment: RT0805BRD07200RL)

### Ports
Ch_In+ (in), Ch_Out (out), Ch_V/C_Switch (in)

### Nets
GND_iso: C32.2 D11.2(K) D12.1 R32.1
Ch_In+: C32.1 D12.2 K2.3(LOAD) ; port Ch_Out, port Ch_In+
Ch_V/C_Switch: R31.2 ; port Ch_V/C_Switch
NetD11_1: D11.1(A) K2.2(CONTROL)
NetK2_1: K2.1(CONTROL+) R31.1
NetK2_4: K2.4(LOAD) R32.2

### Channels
U_TIDA-00764_Signal_Chain/Channel_Inputs/NoCMCh1: designators end in _NoCMCh1; ports Ch_In+=Ch_In+ Ch_Out=Ch_In+ Ch_V/C_Switch=Ch_V/C_Switch
U_TIDA-00764_Signal_Chain/Channel_Inputs/NoCMCh2: designators end in _NoCMCh2; ports Ch_In+=Ch_In+ Ch_Out=Ch_In+ Ch_V/C_Switch=Ch_V/C_Switch
U_TIDA-00764_Signal_Chain/Channel_Inputs/NoCMCh3: designators end in _NoCMCh3; ports Ch_In+=Ch_In+ Ch_Out=Ch_In+ Ch_V/C_Switch=Ch_V/C_Switch
U_TIDA-00764_Signal_Chain/Channel_Inputs/NoCMCh4: designators end in _NoCMCh4; ports Ch_In+=Ch_In+ Ch_Out=Ch_In+ Ch_V/C_Switch=Ch_V/C_Switch

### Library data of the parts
C32 = 06031C103KAT2A: as C28 on sheet TIDA-01333_CMCh_Input
D11 = LB Q39G-L2N2-35-1: as D8 on sheet TIDA-01333_CMCh_Input
D12 = SM6T36CA: as D9 on sheet TIDA-01333_CMCh_Input
K2 = CPC1017N: as K1 on sheet TIDA-01333_CMCh_Input
R31 = CRCW0603180RJNEA: as R29 on sheet TIDA-01333_CMCh_Input
R32 = RT0805BRD07200RL: RES, 200, 0.1%, 0.125 W, 0805; Manufacturer: Yageo America; CompType: Resistor; Value: 200; Value_Code: 200R; Tolerance_%: 0.1; Power_W: 0.125; Value2: 0.125W; VDC_V: 150; TempCo: 25 ppm/C; EIA_Code: E192; U/M: EA; AEC Category: Q200; SizeArea_mm2: 2.5; SizeX_mm: 2; SizeY_mm: 1.25; SizeZ_mm: 1.45

## Sheet TIDA-01333_MUX_Stage.SchDoc
size 431 x 279 mm; Date: Not shown in title block; ApprovedBy: Not shown in title block; CheckedBy: Not shown in title block; Author: Not shown in title block; CompanyName: Not shown in title block; DrawnBy: Tobias Puetz; Engineer: Not shown in title block; Organization: Not shown in title block; Address1: Not shown in title block; Address2: Not shown in title block; Address3: Not shown in title block; Address4: Not shown in title block; DocumentNumber: 10; Revision: Use project parameter SCH_Rev; SheetNumber: 10; SheetTotal: 10; PageSetup: Record=PageOptions¦CenterHorizontal=True¦CenterVertical=True¦PrintScale=1.00¦XCorrection=1.00¦YCorrection=1.00¦PrintKind=0¦BorderSize=5000000¦LeftOffset=0¦BottomOffset=0¦Orientation=2¦PaperLength=1000¦PaperWidth=1000¦Scale=100¦PaperSource=15¦PrintQuality=600¦MediaType=1¦DitherType=10¦PaperKind=Letter¦PrintScaleMode=1
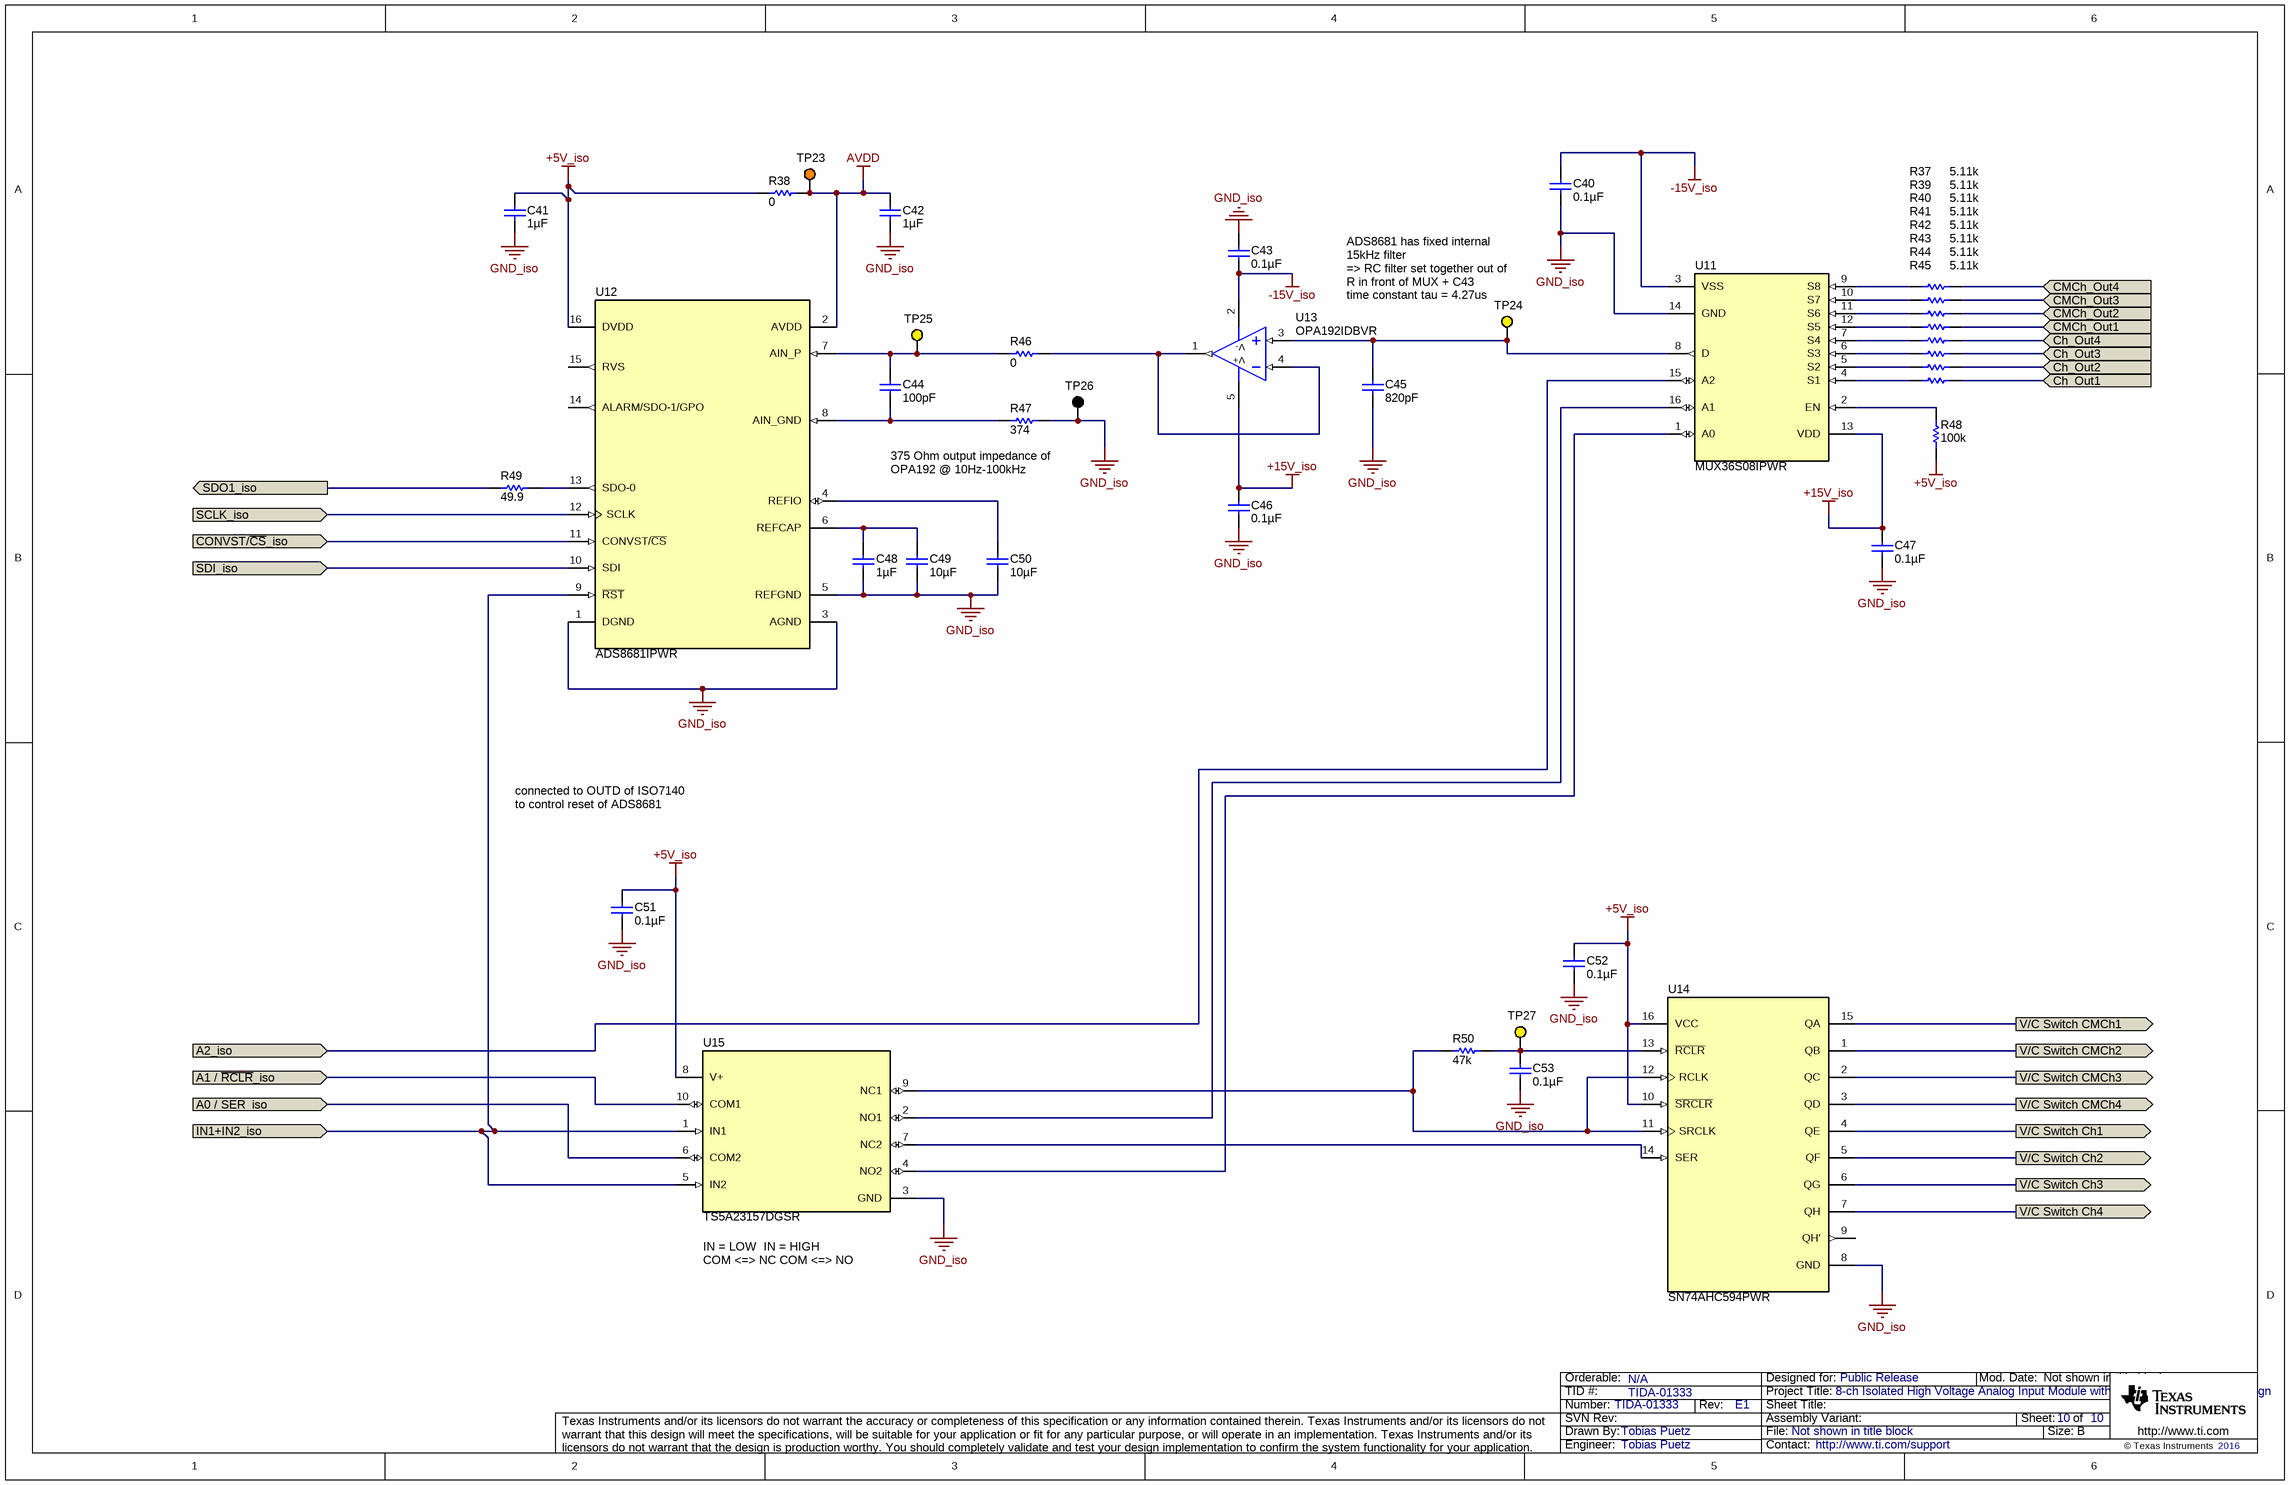
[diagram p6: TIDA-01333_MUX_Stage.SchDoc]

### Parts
C40  ValueDisplayed: 0.1µF  [0603]  (hidden comment: GRM188R71H104KA93D)
C41  ValueDisplayed: 1µF  [0603]  (hidden comment: C1608X7R1C105K080AC)
C42  ValueDisplayed: 1µF  [0603]  (hidden comment: C1608X7R1C105K080AC)
C43  ValueDisplayed: 0.1µF  [0603]  (hidden comment: GRM188R71H104KA93D)
C44  ValueDisplayed: 100pF  [0603]  (hidden comment: GRM1885C1H101JA01D)
C45  ValueDisplayed: 820pF  [0603]  (hidden comment: GRM1885C1H821JA01D)
C46  ValueDisplayed: 0.1µF  [0603]  (hidden comment: GRM188R71H104KA93D)
C47  ValueDisplayed: 0.1µF  [0603]  (hidden comment: GRM188R71H104KA93D)
C48  ValueDisplayed: 1µF  [0603]  (hidden comment: C1608X7R1C105K080AC)
C49  ValueDisplayed: 10µF  [0805_HV]  (hidden comment: C2012X7R1A106K125AC)
C50  ValueDisplayed: 10µF  [0805_HV]  (hidden comment: C2012X7R1A106K125AC)
C51  ValueDisplayed: 0.1µF  [0603]  (hidden comment: GRM188R71H104KA93D)
C52  ValueDisplayed: 0.1µF  [0603]  (hidden comment: GRM188R71H104KA93D)
C53  ValueDisplayed: 0.1µF  [0603]  (hidden comment: GRM188R71H104KA93D)
R37  ValueDisplayed: 5.11k  [0603]  (hidden comment: CRCW06035K11FKEA)
R38  ValueDisplayed: 0  [0603]  (hidden comment: CRCW06030000Z0EA)
R39  ValueDisplayed: 5.11k  [0603]  (hidden comment: CRCW06035K11FKEA)
R40  ValueDisplayed: 5.11k  [0603]  (hidden comment: CRCW06035K11FKEA)
R41  ValueDisplayed: 5.11k  [0603]  (hidden comment: CRCW06035K11FKEA)
R42  ValueDisplayed: 5.11k  [0603]  (hidden comment: CRCW06035K11FKEA)
R43  ValueDisplayed: 5.11k  [0603]  (hidden comment: CRCW06035K11FKEA)
R44  ValueDisplayed: 5.11k  [0603]  (hidden comment: CRCW06035K11FKEA)
R45  ValueDisplayed: 5.11k  [0603]  (hidden comment: CRCW06035K11FKEA)
R46  ValueDisplayed: 0  [0603]  (hidden comment: CRCW06030000Z0EA)
R47  ValueDisplayed: 374  [0603]  (hidden comment: CRCW0603374RFKEA)
R48  ValueDisplayed: 100k  [0603]  (hidden comment: CRCW0603100KJNEA)
R49  ValueDisplayed: 49.9  [0603]  (hidden comment: CRCW060349R9FKEA)
R50  ValueDisplayed: 47k  [0603]  (hidden comment: CRCW060347K0JNEA)
TP23  5003  [Keystone5003]  (value not drawn)
TP24  5004  [Keystone5004]  (value not drawn)
TP25  5004  [Keystone5004]  (value not drawn)
TP26  5001  [Keystone5001]  (value not drawn)
TP27  5004  [Keystone5004]  (value not drawn)
U11  MUX36S08IPWR  [PW0016A_N]
U12  ADS8681IPWR  [PW0016A_N]
U13  OPA192IDBVR  [DBV0005A_N]
U14  SN74AHC594PWR  [PW0016A_N]
U15  TS5A23157DGSR  [DGS0010A_N]

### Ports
A0 / SER_iso (in), A1 / ~{RCLR}_iso (in), A2_iso (in), Ch_Out1 (in), Ch_Out2 (in), Ch_Out3 (in), Ch_Out4 (in), CMCh_Out1 (in), CMCh_Out2 (in), CMCh_Out3 (in), CMCh_Out4 (in), CONVST/~{CS}_iso (in), IN1+IN2_iso (in), SCLK_iso (in), SDI_iso (in), SDO1_iso (out), V/C Switch Ch1 (out), V/C Switch Ch2 (out), V/C Switch Ch3 (out), V/C Switch Ch4 (out), V/C Switch CMCh1 (out), V/C Switch CMCh2 (out), V/C Switch CMCh3 (out), V/C Switch CMCh4 (out)

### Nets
+5V_iso: C41.1 C51.1 C52.1 R38.1 R48.2 U12.16(DVDD) U14.10(~{SRCLR}) U14.16(VCC) U15.8(V+)
+15V_iso: C46.1 C47.1 U11.13(VDD) U13.5(V+)
-15V_iso: C40.2 C43.2 U11.3(VSS) U13.2(V-)
AVDD: C42.1 R38.2 TP23.1 U12.2(AVDD)
GND_iso: C40.1 C41.2 C42.2 C43.1 C45.2 C46.2 C47.2 C48.2 C49.1 C50.1 C51.2 C52.2 C53.2 R47.2 TP26.1 U11.14(GND) U12.1(DGND) U12.3(AGND) U12.5(REFGND) U14.8(GND) U15.3(GND)
A0 / SER_iso: U15.6(COM2) ; port A0 / SER_iso
A1 / ~{RCLR}_iso: U15.10(COM1) ; port A1 / ~{RCLR}_iso
A2_iso: U11.15(A2) ; port A2_iso
Ch_In+: R42.2 ; port Ch_Out4
Ch_In+: R43.2 ; port Ch_Out3  [a separate net that carries the same name]
Ch_In+: R44.2 ; port Ch_Out2  [a separate net that carries the same name]
Ch_In+: R45.2 ; port Ch_Out1  [a separate net that carries the same name]
Ch_V/C_Switch: U14.4(QE) ; port V/C Switch Ch1
Ch_V/C_Switch: U14.5(QF) ; port V/C Switch Ch2  [a separate net that carries the same name]
Ch_V/C_Switch: U14.6(QG) ; port V/C Switch Ch3  [a separate net that carries the same name]
Ch_V/C_Switch: U14.7(QH) ; port V/C Switch Ch4  [a separate net that carries the same name]
CMCh_Out: R41.2 ; port CMCh_Out1
CMCh_Out: R39.2 ; port CMCh_Out3  [a separate net that carries the same name]
CMCh_Out: R40.2 ; port CMCh_Out2  [a separate net that carries the same name]
CMCh_Out: R37.2 ; port CMCh_Out4  [a separate net that carries the same name]
CMCh_V/C_Switch: U14.15(QA) ; port V/C Switch CMCh1
CMCh_V/C_Switch: U14.2(QC) ; port V/C Switch CMCh3  [a separate net that carries the same name]
CMCh_V/C_Switch: U14.1(QB) ; port V/C Switch CMCh2  [a separate net that carries the same name]
CMCh_V/C_Switch: U14.3(QD) ; port V/C Switch CMCh4  [a separate net that carries the same name]
CONVST/~{CS}_iso: U12.11(CONVST/~{CS}) ; port CONVST/~{CS}_iso
IN1+IN2_iso: U12.9(~{RST}) U15.1(IN1) U15.5(IN2) ; port IN1+IN2_iso
SCLK_iso: U12.12(SCLK) ; port SCLK_iso
SDI_iso: U12.10(SDI) ; port SDI_iso
SDO1_iso: R49.1 ; port SDO1_iso
NetC44_1: C44.1 R46.1 TP25.1 U12.7(AIN_P)
NetC44_2: C44.2 R47.1 U12.8(AIN_GND)
NetC45_1: C45.1 TP24.1 U11.8(D) U13.3(IN+)
NetC48_1: C48.1 C49.2 U12.6(REFCAP)
NetC50_2: C50.2 U12.4(REFIO)
NetC53_1: C53.1 R50.2 TP27.1 U14.13(~{RCLR})
NetR37_1: R37.1 U11.9(S8)
NetR39_1: R39.1 U11.10(S7)
NetR40_1: R40.1 U11.11(S6)
NetR41_1: R41.1 U11.12(S5)
NetR42_1: R42.1 U11.7(S4)
NetR43_1: R43.1 U11.6(S3)
NetR44_1: R44.1 U11.5(S2)
NetR45_1: R45.1 U11.4(S1)
NetR46_2: R46.2 U13.1(OUT) U13.4(IN-)
NetR48_1: R48.1 U11.2(EN)
NetR49_2: R49.2 U12.13(SDO-0)
NetR50_1: R50.1 U14.11(SRCLK) U14.12(RCLK) U15.9(NC1)
NetU11_1: U11.1(A0) U15.4(NO2)
NetU11_16: U11.16(A1) U15.2(NO1)
NetU14_14: U14.14(SER) U15.7(NC2)

Not connected (* = marked no-connect by the designer): U12 14(ALARM/SDO-1/GPO) 15(RVS); U14 9(QH')

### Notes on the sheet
- (near TP24) ADS8681 has fixed internal 15kHz filter
  => RC filter set together out of R in front of MUX + C43
  time constant tau = 4.27us
- 375 Ohm output impedance of OPA192 @ 10Hz-100kHz
- connected to OUTD of ISO7140 to control reset of ADS8681
- (near U15) IN = LOW		IN = HIGH
  COM <=> NC	COM <=> NO

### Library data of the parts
C40 C43 C46 C47 C51-C53 = GRM188R71H104KA93D: as C25 on sheet TIDA-01333_CMCh_Input
C41 C42 C48 = C1608X7R1C105K080AC: as C26 on sheet TIDA-01333_CMCh_Input
C44 = GRM1885C1H101JA01D: CAP, CERM, 100 pF, 50 V, +/- 5%, C0G/NP0, 0603; Manufacturer: MuRata; Polarized: N; CompType: Capacitor; Value: 100pF; U/M: EA; Cap_F: 0.0000000001; Tolerance_%: 5; Value1: Unknown; VDC_V: 50; Value2: 50V; TaMin_C: -55; TaMax_C: 125; SizeArea_mm2: 1.28; SizeAreaWB_mm2: 4.68; SizeX_mm: 1.6; SizeY_mm: 0.8; SizeZ_mm: 1; AEC Category: Q200
C45 = GRM1885C1H821JA01D: CAP, CERM, 820 pF, 50 V, +/- 5%, C0G/NP0, 0603; Manufacturer: MuRata; Polarized: N; CompType: Capacitor; Value: 820pF; U/M: EA; Cap_F: 0.00000000082; Tolerance_%: 5; Value1: Unknown; VDC_V: 50; Value2: 50V; TaMin_C: -55; TaMax_C: 125; SizeArea_mm2: 1.28; SizeAreaWB_mm2: 4.68; SizeX_mm: 1.6; SizeY_mm: 0.8; SizeZ_mm: 1; AEC Category: Q200
C49 C50 = C2012X7R1A106K125AC: CAP, CERM, 10 µF, 10 V, +/- 10%, X7R, 0805; Manufacturer: TDK; Polarized: N; CompType: Capacitor; Value: 10uF; U/M: EA; Cap_F: 0.00001; Tolerance_%: 10; ESR_ohm: 0.001063; Value1: 0.001063 ohm; Value2: 10V; IRMS_A: 6.32908; TaMin_C: -55; TaMax_C: 125; Cap_Case: 0805; AEC Category: Q200; SizeArea_mm2: 2.5; SizeAreaWB_mm2: 6.75; SizeX_mm: 2; SizeY_mm: 1.25; SizeZ_mm: 1.45
R37 R39-R45 = CRCW06035K11FKEA: RES, 5.11 k, 1%, 0.1 W, 0603; Manufacturer: Vishay-Dale; CompType: Resistor; Value: 5.11k; Res_ohm: 5110; Value_Code: 5k11; Tolerance_%: 1; Power_W: 0.1; Value2: 0.1W; VDC_V: 75; TempCo: 100 ppm/C; EIA_Code: E96; U/M: EA; AEC Category: Q200; SizeArea_mm2: 1.28; SizeX_mm: 1.6; SizeY_mm: 0.8
R38 R46 = CRCW06030000Z0EA: as R5 on sheet TIDA-01333_Cape
R47 = CRCW0603374RFKEA: RES, 374, 1%, 0.1 W, 0603; Manufacturer: Vishay-Dale; CompType: Resistor; Value: 374; Value_Code: 374R; Tolerance_%: 1; Power_W: 0.1; Value2: 0.1W; VDC_V: 75; TempCo: 100 ppm/C; EIA_Code: E96; U/M: EA; AEC Category: Q200; SizeArea_mm2: 1.28; SizeX_mm: 1.6; SizeY_mm: 0.8
R48 = CRCW0603100KJNEA: RES, 100 k, 5%, 0.1 W, 0603; Manufacturer: Vishay-Dale; CompType: Resistor; Value: 100k; Res_ohm: 100000; Tolerance_%: 5; Power_W: 0.1; Value2: 0.1W; VDC_V: 75; TempCo: 200 ppm/C; EIA_Code: E24; U/M: EA; AEC Category: Q200; SizeArea_mm2: 1.28; SizeX_mm: 1.6; SizeY_mm: 0.8; SizeZ_mm: 1
R49 = CRCW060349R9FKEA: RES, 49.9, 1%, 0.1 W, 0603; Manufacturer: Vishay-Dale; CompType: Resistor; Value: 49.9; Value_Code: 49R9; Tolerance_%: 1; Power_W: 0.1; Value2: 0.1W; VDC_V: 75; TempCo: 100 ppm/C; SizeArea_mm2: 1.28; SizeX_mm: 1.6; SizeY_mm: 0.8; EIA_Code: E96; U/M: EA; AEC Category: Q200
R50 = CRCW060347K0JNEA: RES, 47 k, 5%, 0.1 W, 0603; Manufacturer: Vishay-Dale; CompType: Resistor; Value: 47k; Res_ohm: 47000; Value_Code: 47k0; Tolerance_%: 5; Power_W: 0.1; Value2: 0.1W; VDC_V: 75; TempCo: 200 ppm/C; EIA_Code: E24; U/M: EA; AEC Category: Q200; SizeArea_mm2: 1.28; SizeX_mm: 1.6; SizeY_mm: 0.8; SizeZ_mm: 1
TP23 = 5003: Test Point, Miniature, Orange, TH; Manufacturer: Keystone; CompType: Test Point Loop; ContactFinish: Silver
TP24 TP25 TP27 = 5004: Test Point, Miniature, Yellow, TH; Manufacturer: Keystone; CompType: Test Point Loop; ContactFinish: Silver
TP26 = 5001: as TP12 on sheet TIDA-01333_Signal_Chain
U11 = MUX36S08IPWR: MUX36xxx 36-V, Low-Capacitance, Low-Leakage-Current, Precision, Analog Multiplexers, PW0016A (TSSOP-16); Manufacturer: Texas Instruments; SymbolCreator: Altium; SizeArea_mm2: 32; SizeAreaWB_mm2: 58.8; SizeX_mm: 6.4; SizeY_mm: 5; SizeZ_mm: 1.2; CompType: IC; U/M: EA
U12 = ADS8681IPWR: 16-bit, 1 MSPS, 5V SAR ADC with Integrated Analog Front End & Bipolar Inputs, PW0016A (TSSOP-16); Manufacturer: Texas Instruments; SymbolCreator: Altium; SizeArea_mm2: 32; SizeAreaWB_mm2: 58.8; SizeX_mm: 6.4; SizeY_mm: 5; SizeZ_mm: 1.2; CompType: IC; U/M: EA
U13 = OPA192IDBVR: 36-V, Precision, Rail-to-Rail Input/Output, Low Offset Voltage, Low Input Bias Current Op Amp with e-trim, DBV0005A; Alternate PartNumber: OPA192IDBVT; Manufacturer: Texas Instruments; SizeX_mm: 2.8; SizeY_mm: 2.9; SizeZ_mm: 1.45; CompType: IC; U/M: EA; SizeArea_mm2: 8.12; SizeAreaWB_mm2: 14.82
U14 = SN74AHC594PWR: 8-Bit Shift Register With Output Registers, PW0016A; Manufacturer: Texas Instruments; SymbolCreator: Altium; CompType: IC; U/M: EA; SizeArea_mm2: 32; SizeAreaWB_mm2: 58.8; SizeX_mm: 6.4; SizeY_mm: 5; SizeZ_mm: 1.2
U15 = TS5A23157DGSR: DUAL 10-Ohm SPDT ANALOG SWITCH, DGS0010A; Alternate PartNumber: TS5A23157DGST; Manufacturer: Texas Instruments; SymbolCreator: Altium; CompType: IC; U/M: EA; SizeArea_mm2: 14.7; SizeAreaWB_mm2: 23.6; SizeX_mm: 4.9; SizeY_mm: 3; SizeZ_mm: 1.1

## Sheet TIDA-01333_Digital_Isolation.SchDoc: Digital Isolation
size 431 x 279 mm; Date: Not shown in title block; ApprovedBy: Not shown in title block; CheckedBy: Not shown in title block; Author: Not shown in title block; CompanyName: Not shown in title block; DrawnBy: Tobias Puetz; Engineer: Not shown in title block; Organization: Not shown in title block; Address1: Not shown in title block; Address2: Not shown in title block; Address3: Not shown in title block; Address4: Not shown in title block; DocumentNumber: 9; Revision: Use project parameter SCH_Rev; SheetNumber: 9; SheetTotal: 10; PageSetup: Record=PageOptions¦CenterHorizontal=True¦CenterVertical=True¦PrintScale=1.00¦XCorrection=1.00¦YCorrection=1.00¦PrintKind=0¦BorderSize=5000000¦LeftOffset=0¦BottomOffset=0¦Orientation=2¦PaperLength=1000¦PaperWidth=1000¦Scale=100¦PaperSource=15¦PrintQuality=600¦MediaType=1¦DitherType=10¦PaperKind=Letter¦PrintScaleMode=1
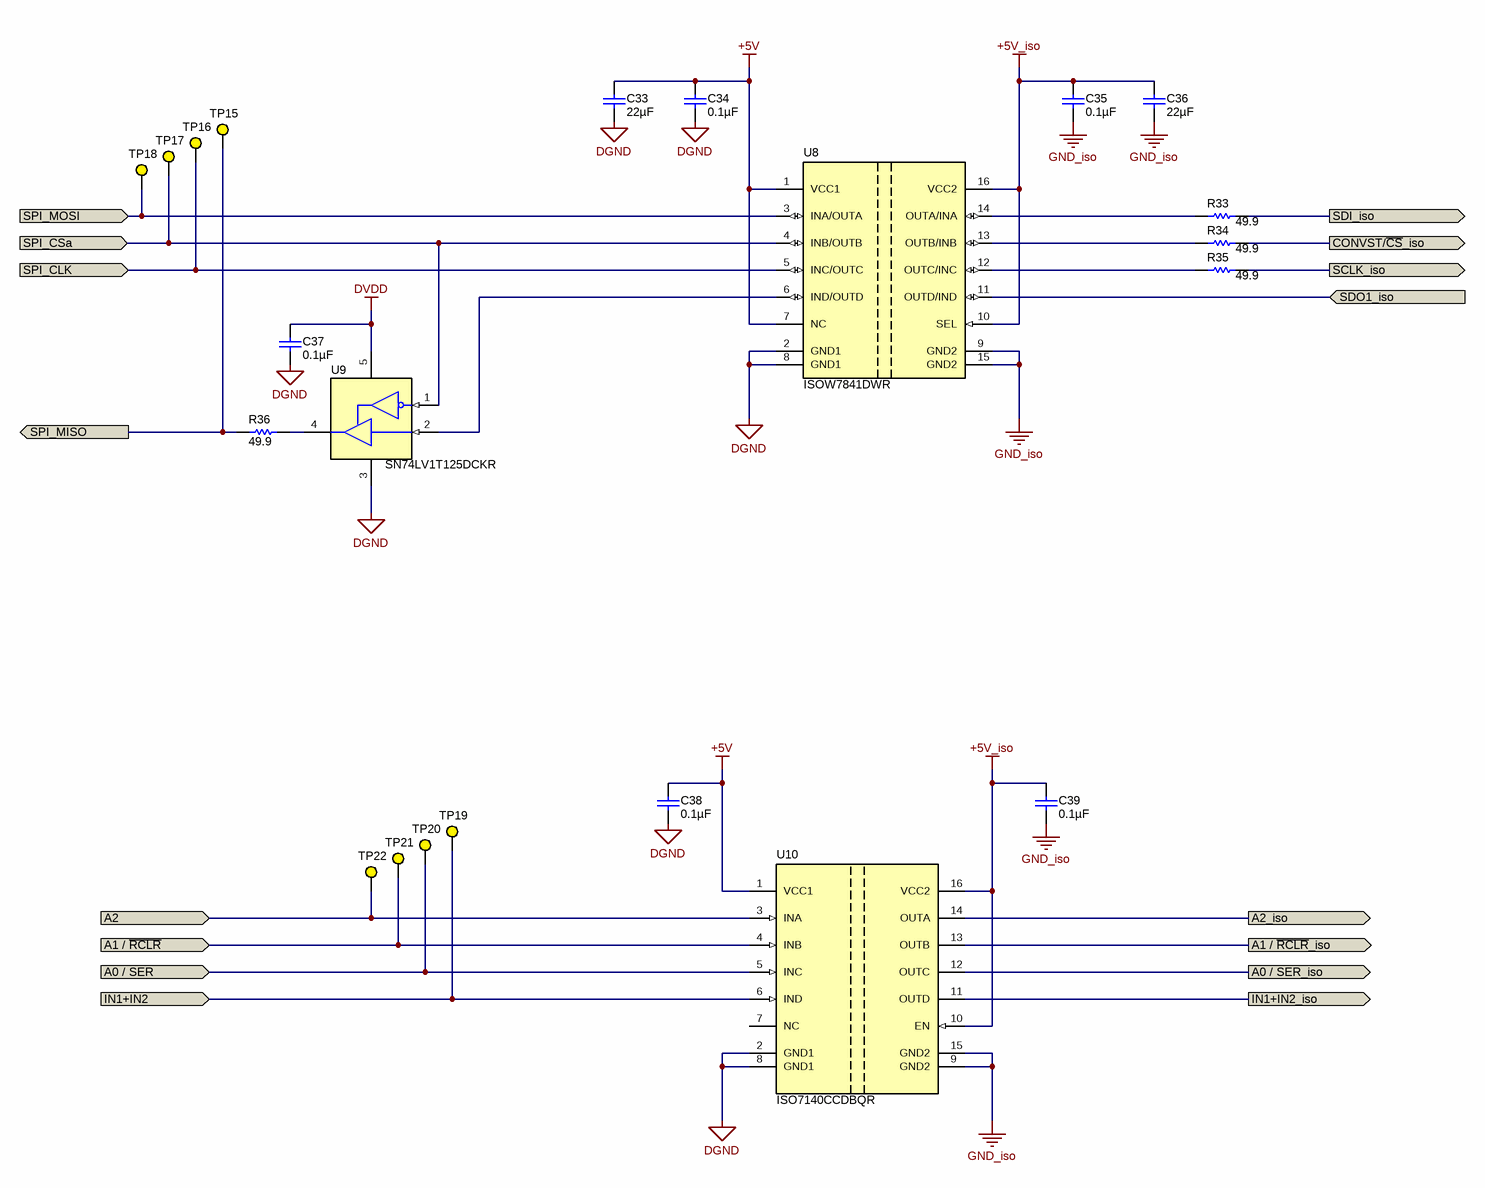
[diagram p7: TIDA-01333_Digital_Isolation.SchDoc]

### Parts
C33  ValueDisplayed: 22µF  [1206_180]  (hidden comment: GRM31CR71A226KE15L)
C34  ValueDisplayed: 0.1µF  [0603]  (hidden comment: GRM188R71H104KA93D)
C35  ValueDisplayed: 0.1µF  [0603]  (hidden comment: GRM188R71H104KA93D)
C36  ValueDisplayed: 22µF  [1206_180]  (hidden comment: GRM31CR71A226KE15L)
C37  ValueDisplayed: 0.1µF  [0603]  (hidden comment: GRM188R71H104KA93D)
C38  ValueDisplayed: 0.1µF  [0603]  (hidden comment: GRM188R71H104KA93D)
C39  ValueDisplayed: 0.1µF  [0603]  (hidden comment: GRM188R71H104KA93D)
R33  ValueDisplayed: 49.9  [0603]  (hidden comment: CRCW060349R9FKEA)
R34  ValueDisplayed: 49.9  [0603]  (hidden comment: CRCW060349R9FKEA)
R35  ValueDisplayed: 49.9  [0603]  (hidden comment: CRCW060349R9FKEA)
R36  ValueDisplayed: 49.9  [0603]  (hidden comment: CRCW060349R9FKEA)
TP15  5004  [Keystone5004]  (value not drawn)
TP16  5004  [Keystone5004]  (value not drawn)
TP17  5004  [Keystone5004]  (value not drawn)
TP18  5004  [Keystone5004]  (value not drawn)
TP19  5004  [Keystone5004]  (value not drawn)
TP20  5004  [Keystone5004]  (value not drawn)
TP21  5004  [Keystone5004]  (value not drawn)
TP22  5004  [Keystone5004]  (value not drawn)
U8  ISOW7841DWR  [DW0016B_N]
U9  SN74LV1T125DCKR  [DCK0005A_N]
U10  ISO7140CCDBQR  [DBQ0016A_N]

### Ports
A0 / SER (in), A0 / SER_iso (out), A1 / ~{RCLR} (in), A1 / ~{RCLR}_iso (out), A2 (in), A2_iso (out), CONVST/~{CS}_iso (out), IN1+IN2 (in), IN1+IN2_iso (out), SCLK_iso (out), SDI_iso (out), SDO1_iso (in), SPI_CLK (in), SPI_CSa (in), SPI_MISO (out), SPI_MOSI (in)

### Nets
+5V: C33.1 C34.1 C38.1 U8.1(VCC1) U8.7(NC) U10.1(VCC1)
+5V_iso: C35.1 C36.1 C39.1 U8.10(SEL) U8.16(VCC2) U10.10(EN) U10.16(VCC2)
DGND: C33.2 C34.2 C37.2 C38.2 U8.2(GND1) U8.8(GND1) U9.3(GND) U10.2(GND1) U10.8(GND1)
DVDD: C37.1 U9.5(VCC)
GND_iso: C35.2 C36.2 C39.2 U8.9(GND2) U8.15(GND2) U10.9(GND2) U10.15(GND2)
A0 / SER: TP20.1 U10.5(INC) ; port A0 / SER
A0 / SER_iso: U10.12(OUTC) ; port A0 / SER_iso
A1 / ~{RCLR}: TP21.1 U10.4(INB) ; port A1 / ~{RCLR}
A1 / ~{RCLR}_iso: U10.13(OUTB) ; port A1 / ~{RCLR}_iso
A2: TP22.1 U10.3(INA) ; port A2
A2_iso: U10.14(OUTA) ; port A2_iso
CONVST/~{CS}_iso: R34.2 ; port CONVST/~{CS}_iso
IN1+IN2: TP19.1 U10.6(IND) ; port IN1+IN2
IN1+IN2_iso: U10.11(OUTD) ; port IN1+IN2_iso
SCLK_iso: R35.2 ; port SCLK_iso
SDI_iso: R33.2 ; port SDI_iso
SDO1_iso: U8.11(OUTD/IND) ; port SDO1_iso
SPI_CLK: TP16.1 U8.5(INC/OUTC) ; port SPI_CLK
SPI_CSa: TP17.1 U8.4(INB/OUTB) U9.1(~{OE}) ; port SPI_CSa
SPI_MISO: R36.1 TP15.1 ; port SPI_MISO
SPI_MOSI: TP18.1 U8.3(INA/OUTA) ; port SPI_MOSI
NetR33_1: R33.1 U8.14(OUTA/INA)
NetR34_1: R34.1 U8.13(OUTB/INB)
NetR35_1: R35.1 U8.12(OUTC/INC)
NetR36_2: R36.2 U9.4(Y)
NetU8_6: U8.6(IND/OUTD) U9.2(A)

Not connected (* = marked no-connect by the designer): U10 7(NC)

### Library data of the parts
C33 C36 = GRM31CR71A226KE15L: CAP, CERM, 22 µF, 10 V, +/- 10%, X7R, 1206; Manufacturer: MuRata; Polarized: N; CompType: Capacitor; Value: 22uF; U/M: EA; Cap_F: 0.000022; Tolerance_%: 10; Value1: Unknown; Value2: 10V; TaMin_C: -55; TaMax_C: 125; Cap_Case: 1206; AEC Category: Q200; SizeArea_mm2: 5.12; SizeAreaWB_mm2: 10.92; SizeX_mm: 3.2; SizeY_mm: 1.6; SizeZ_mm: 1.8
C34 C35 C37-C39 = GRM188R71H104KA93D: as C25 on sheet TIDA-01333_CMCh_Input
R33-R36 = CRCW060349R9FKEA: as R49 on sheet TIDA-01333_MUX_Stage
TP15-TP22 = 5004: as TP24 on sheet TIDA-01333_MUX_Stage
U8 = ISOW7841DWR: ISOW7841DW, DW0016B; Manufacturer: Texas Instruments; SymbolCreator: a0411947; SizeArea_mm2: 107.12; SizeAreaWB_mm2: 152.52; SizeX_mm: 10.4; SizeY_mm: 10.3; SizeZ_mm: 2.65; CompType: IC; U/M: EA
U9 = SN74LV1T125DCKR: Single Power Supply Single Buffer Gate with 3-State Output CMOS Logic Level Shifter, DCK0005A; Manufacturer: Texas Instruments; SymbolCreator: Altium; SizeArea_mm2: 4.2; SizeAreaWB_mm2: 9.3; SizeX_mm: 2.1; SizeY_mm: 2; SizeZ_mm: 1.1; CompType: IC; U/M: EA
U10 = ISO7140CCDBQR: 4242-VPK Small-Footprint and Low-Power Quad Channels Digital Isolators, DBQ0016A; Manufacturer: Texas Instruments; SymbolCreator: a0799628; CompType: IC; U/M: EA; SizeArea_mm2: 60; SizeAreaWB_mm2: 96; SizeX_mm: 6; SizeY_mm: 10; SizeZ_mm: 1.75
